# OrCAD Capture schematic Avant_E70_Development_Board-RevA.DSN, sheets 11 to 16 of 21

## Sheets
11 Bank-9,10,11 LPDDR4: size D; title: Bank-9,10,11 LPDDR4
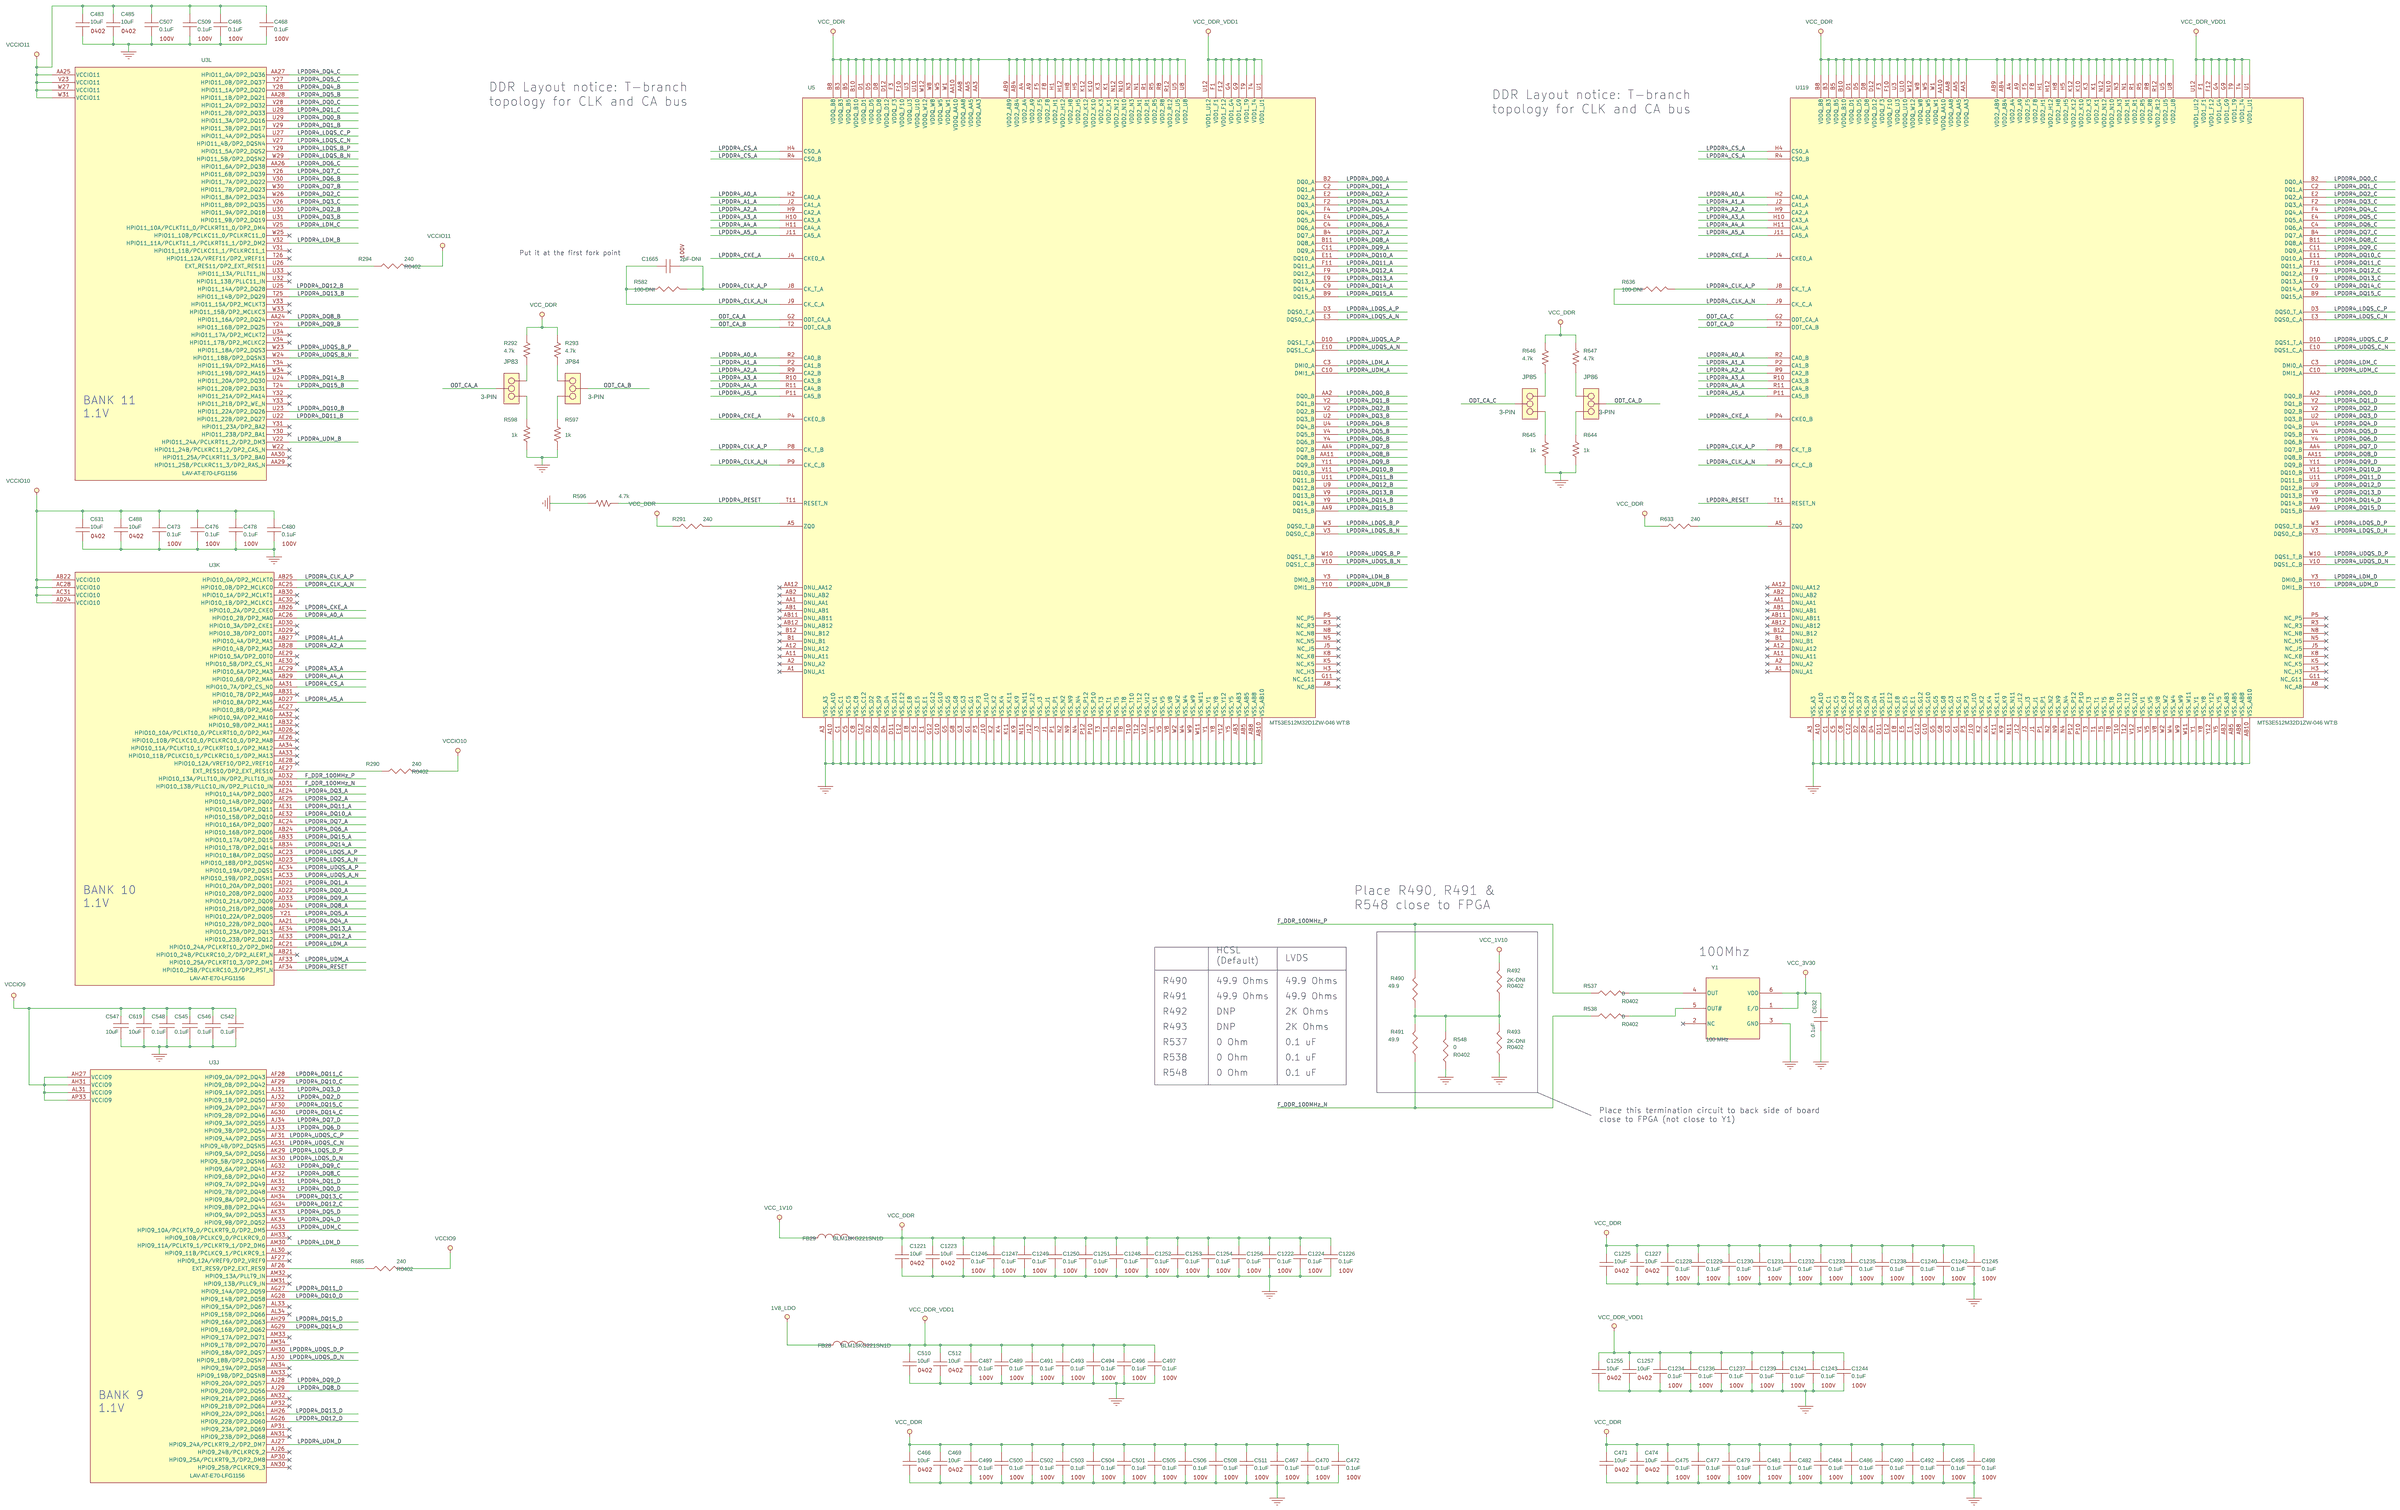
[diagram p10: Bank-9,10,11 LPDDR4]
12 Bank-12,13 PMODs: size B; title: Bank-12,13 PMODs
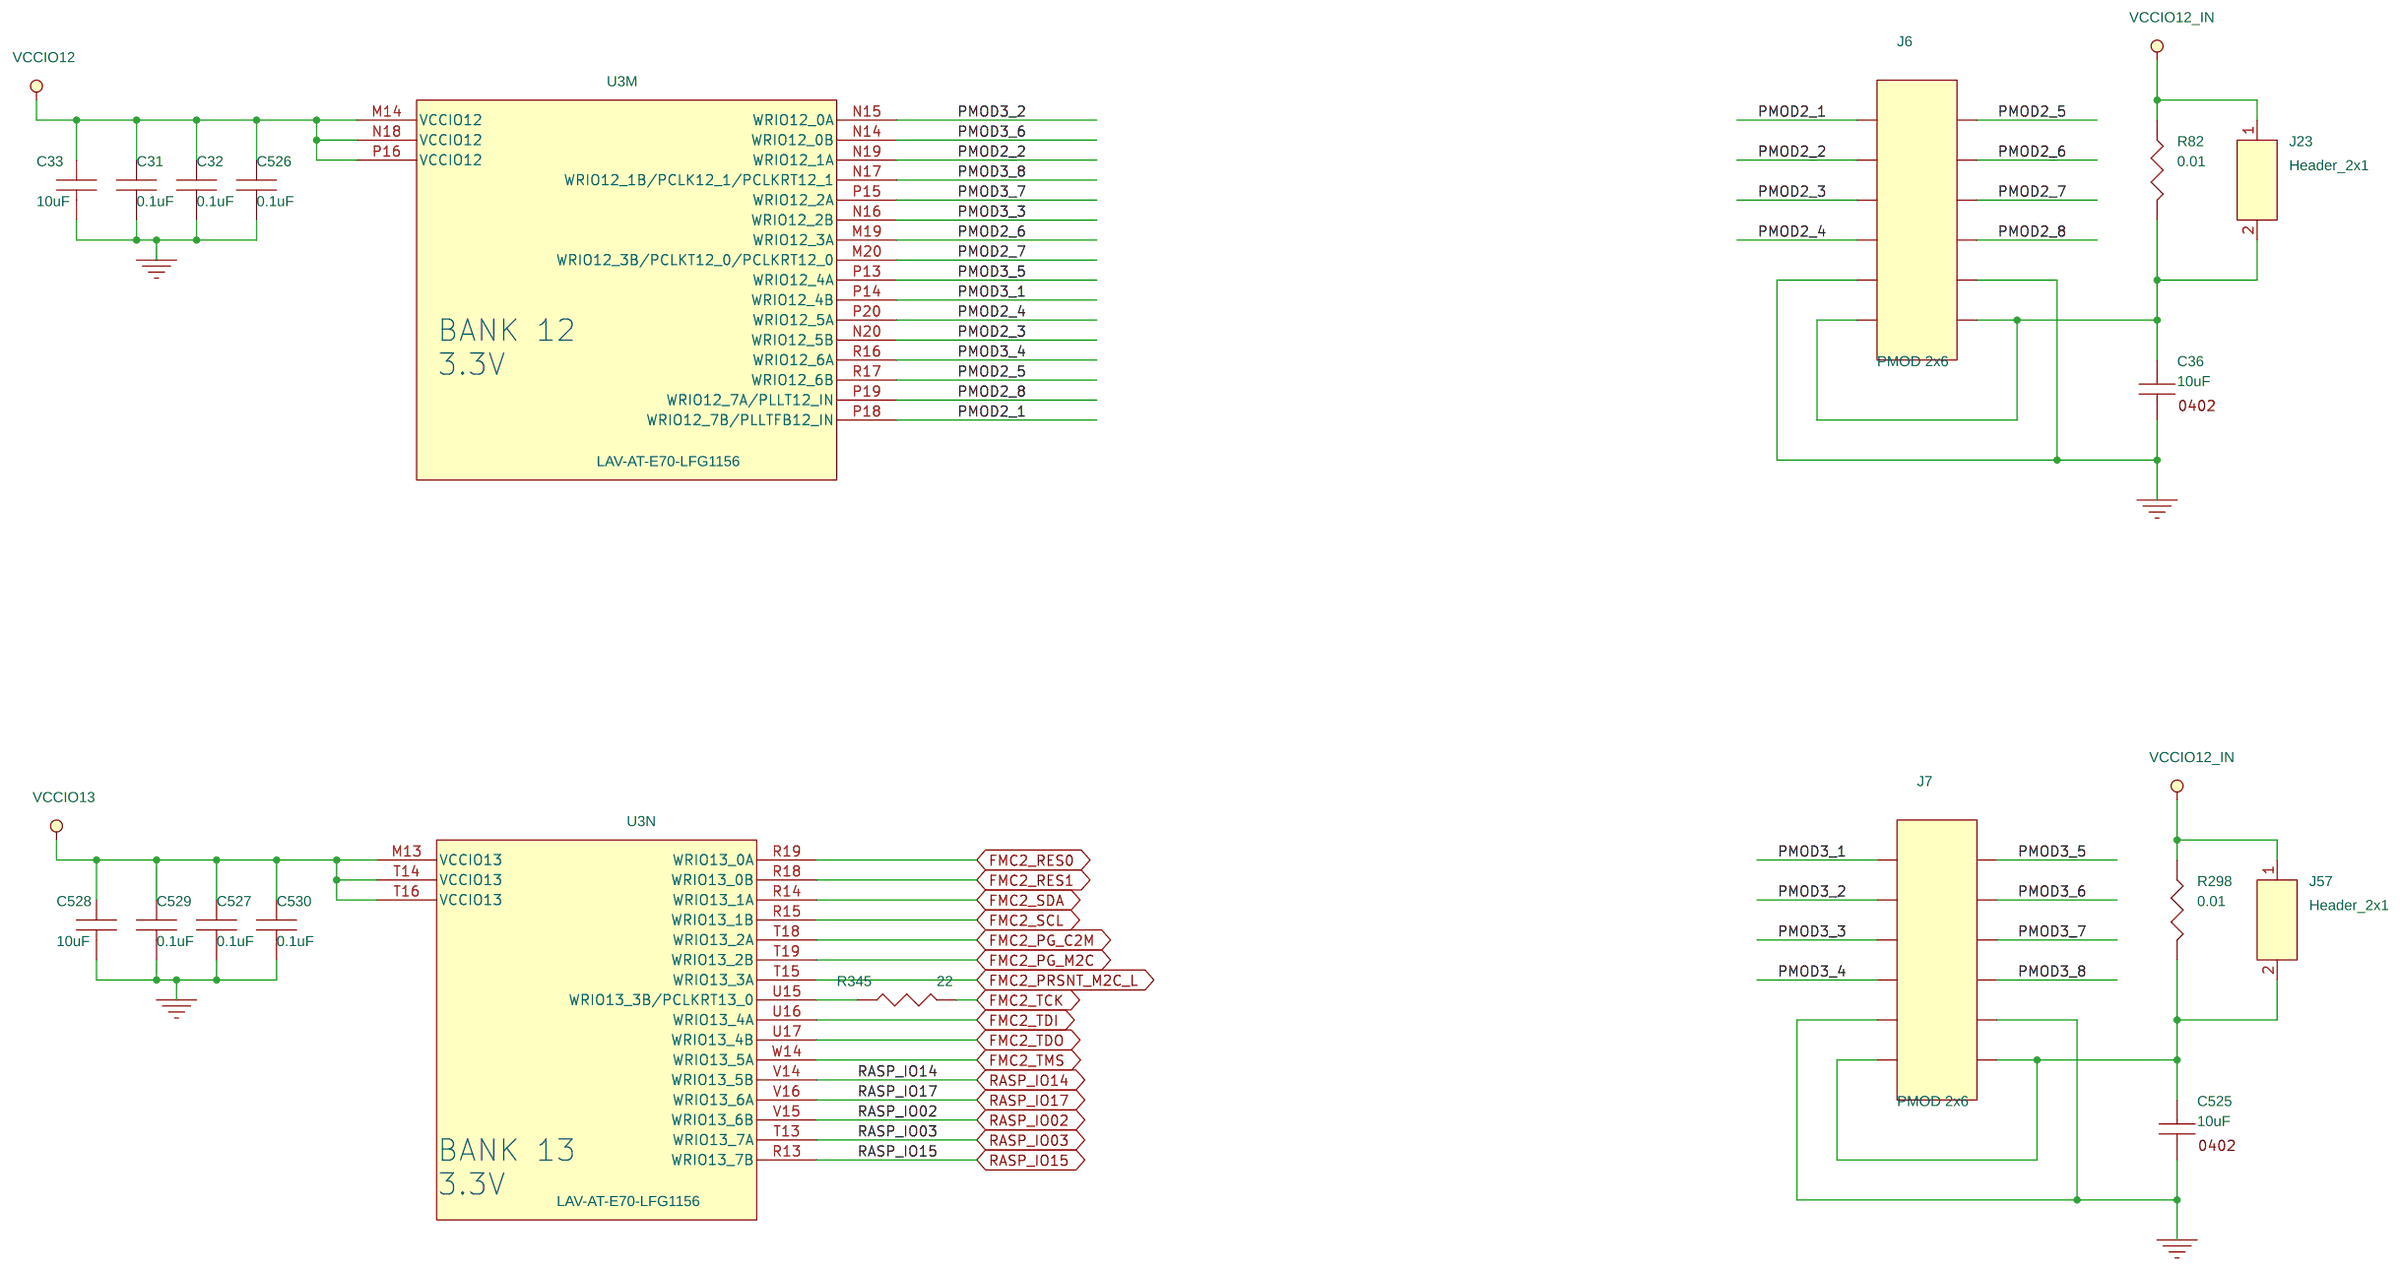
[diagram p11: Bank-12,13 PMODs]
13 Bank-14 Segment & RPi: size B; title: Bank-14 Segment & RPi
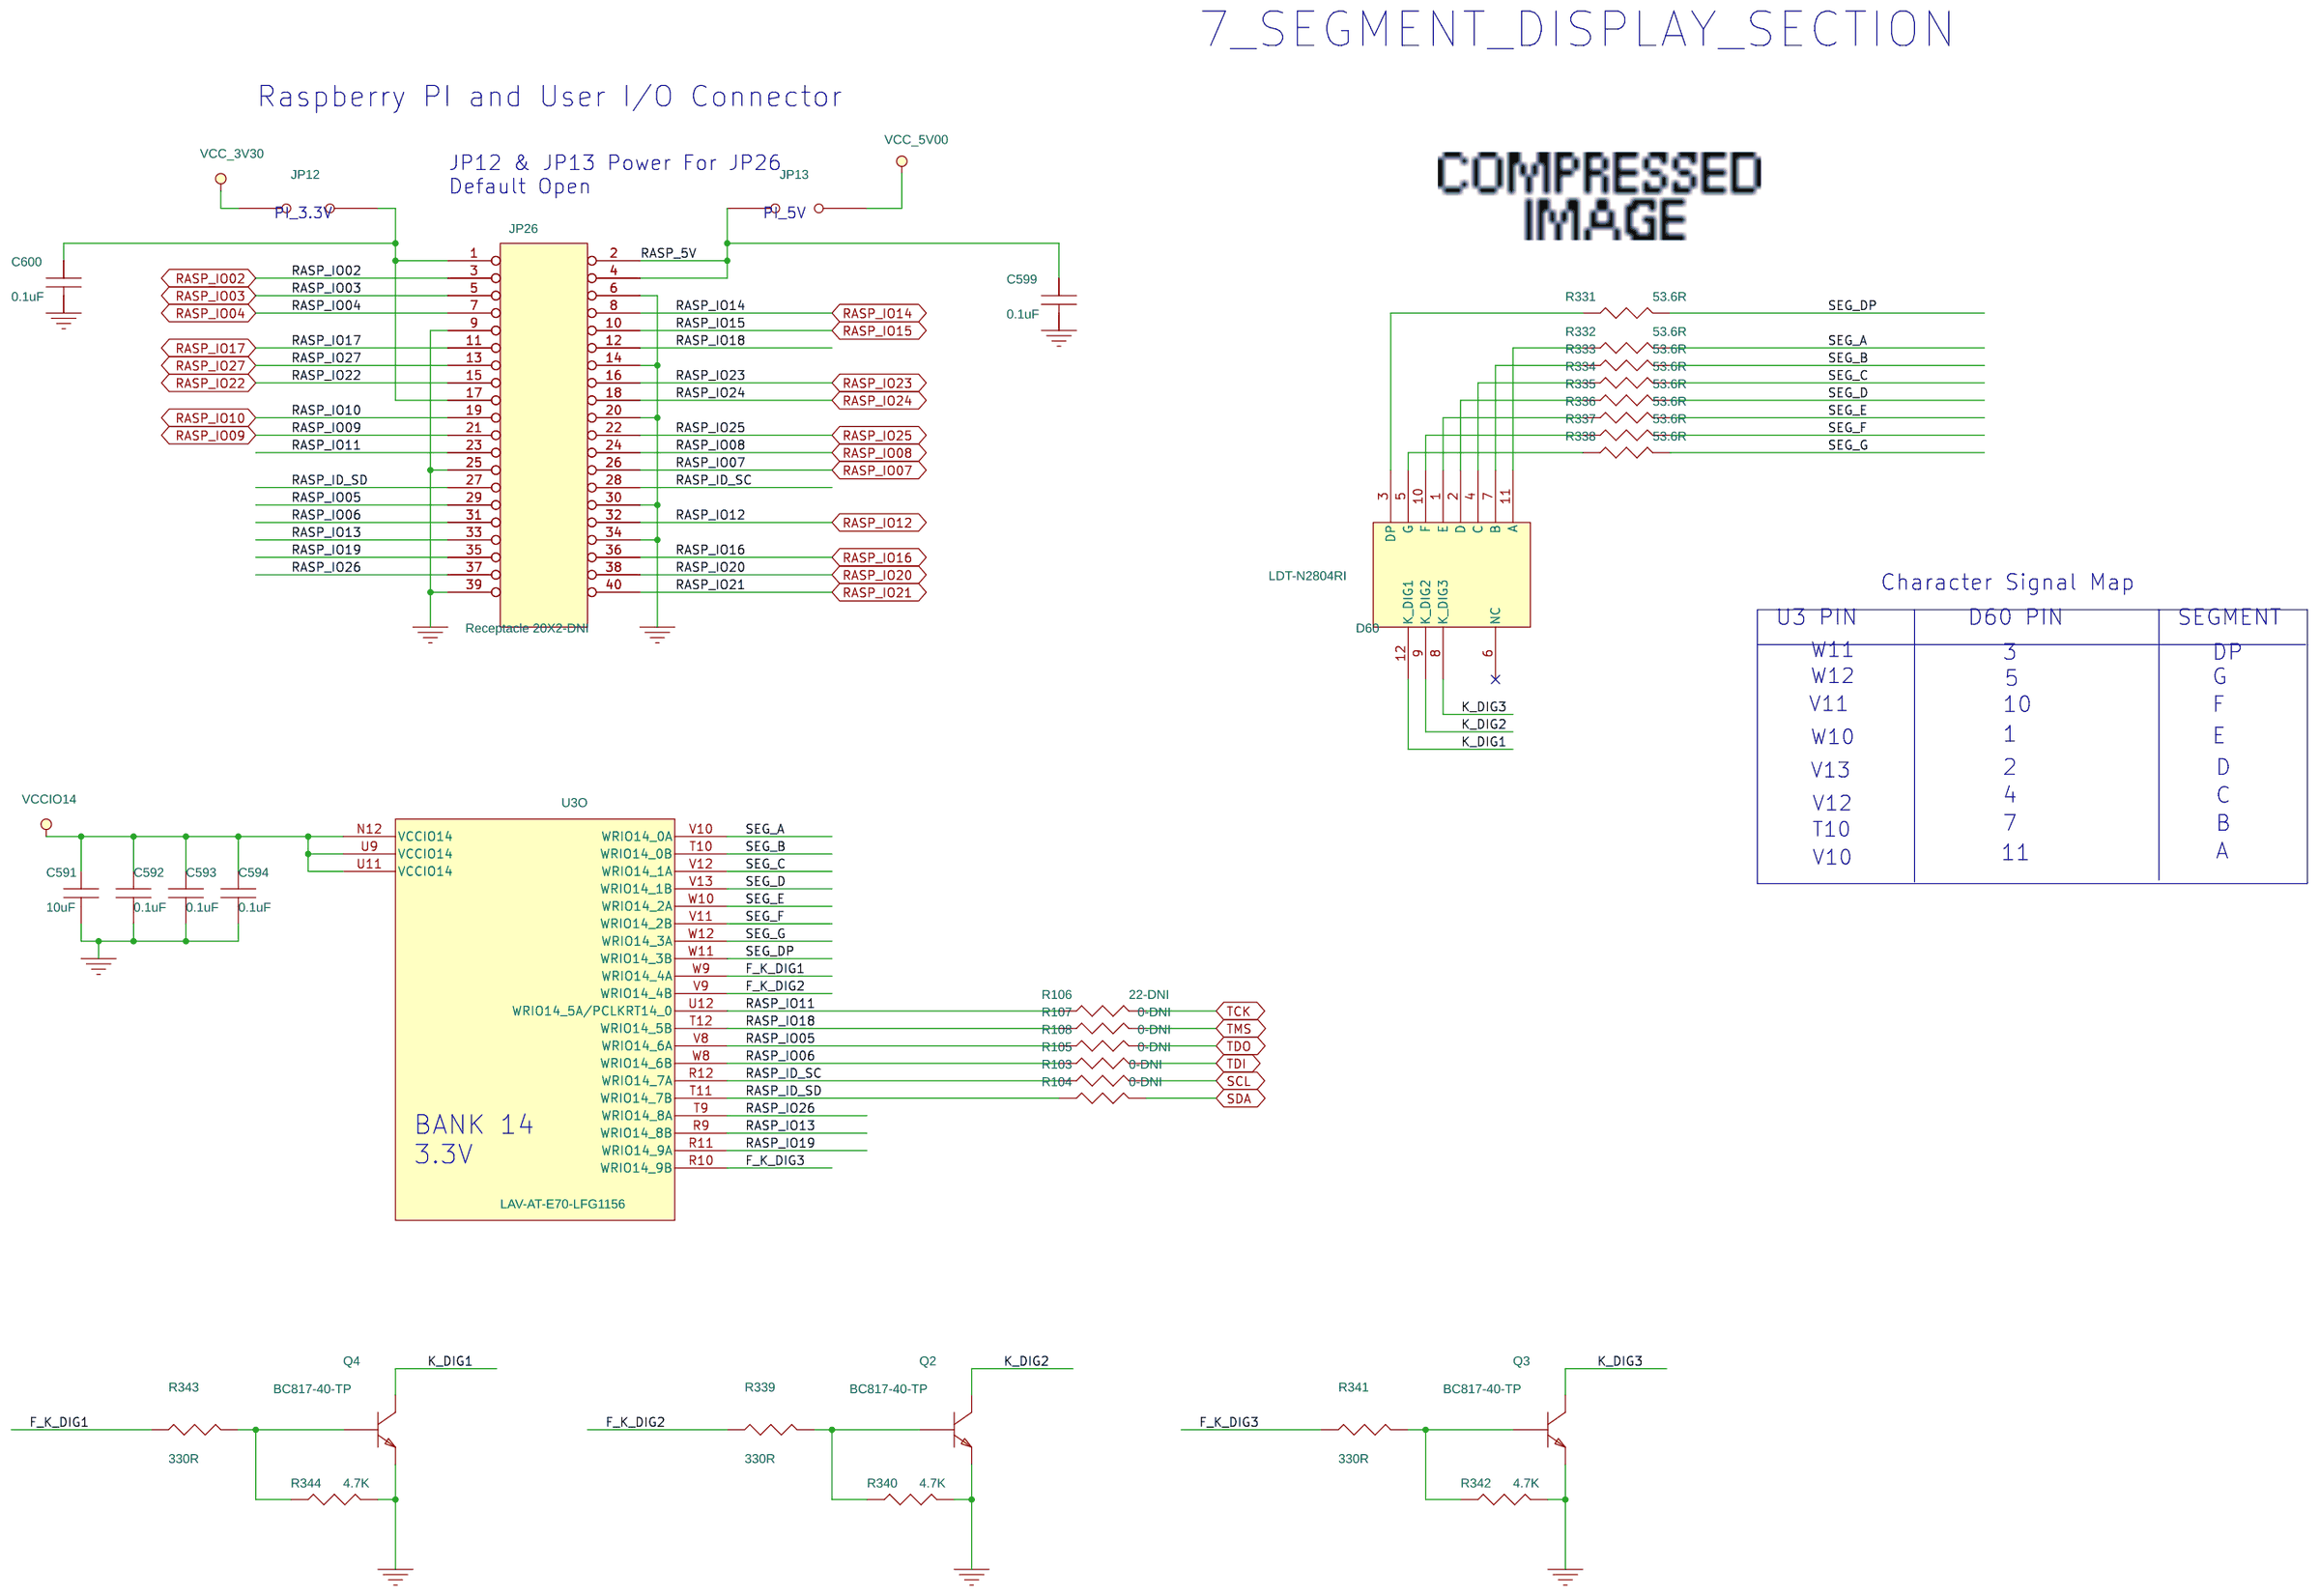
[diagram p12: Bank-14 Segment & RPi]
14 Bank Power: size B; title: Bank Power
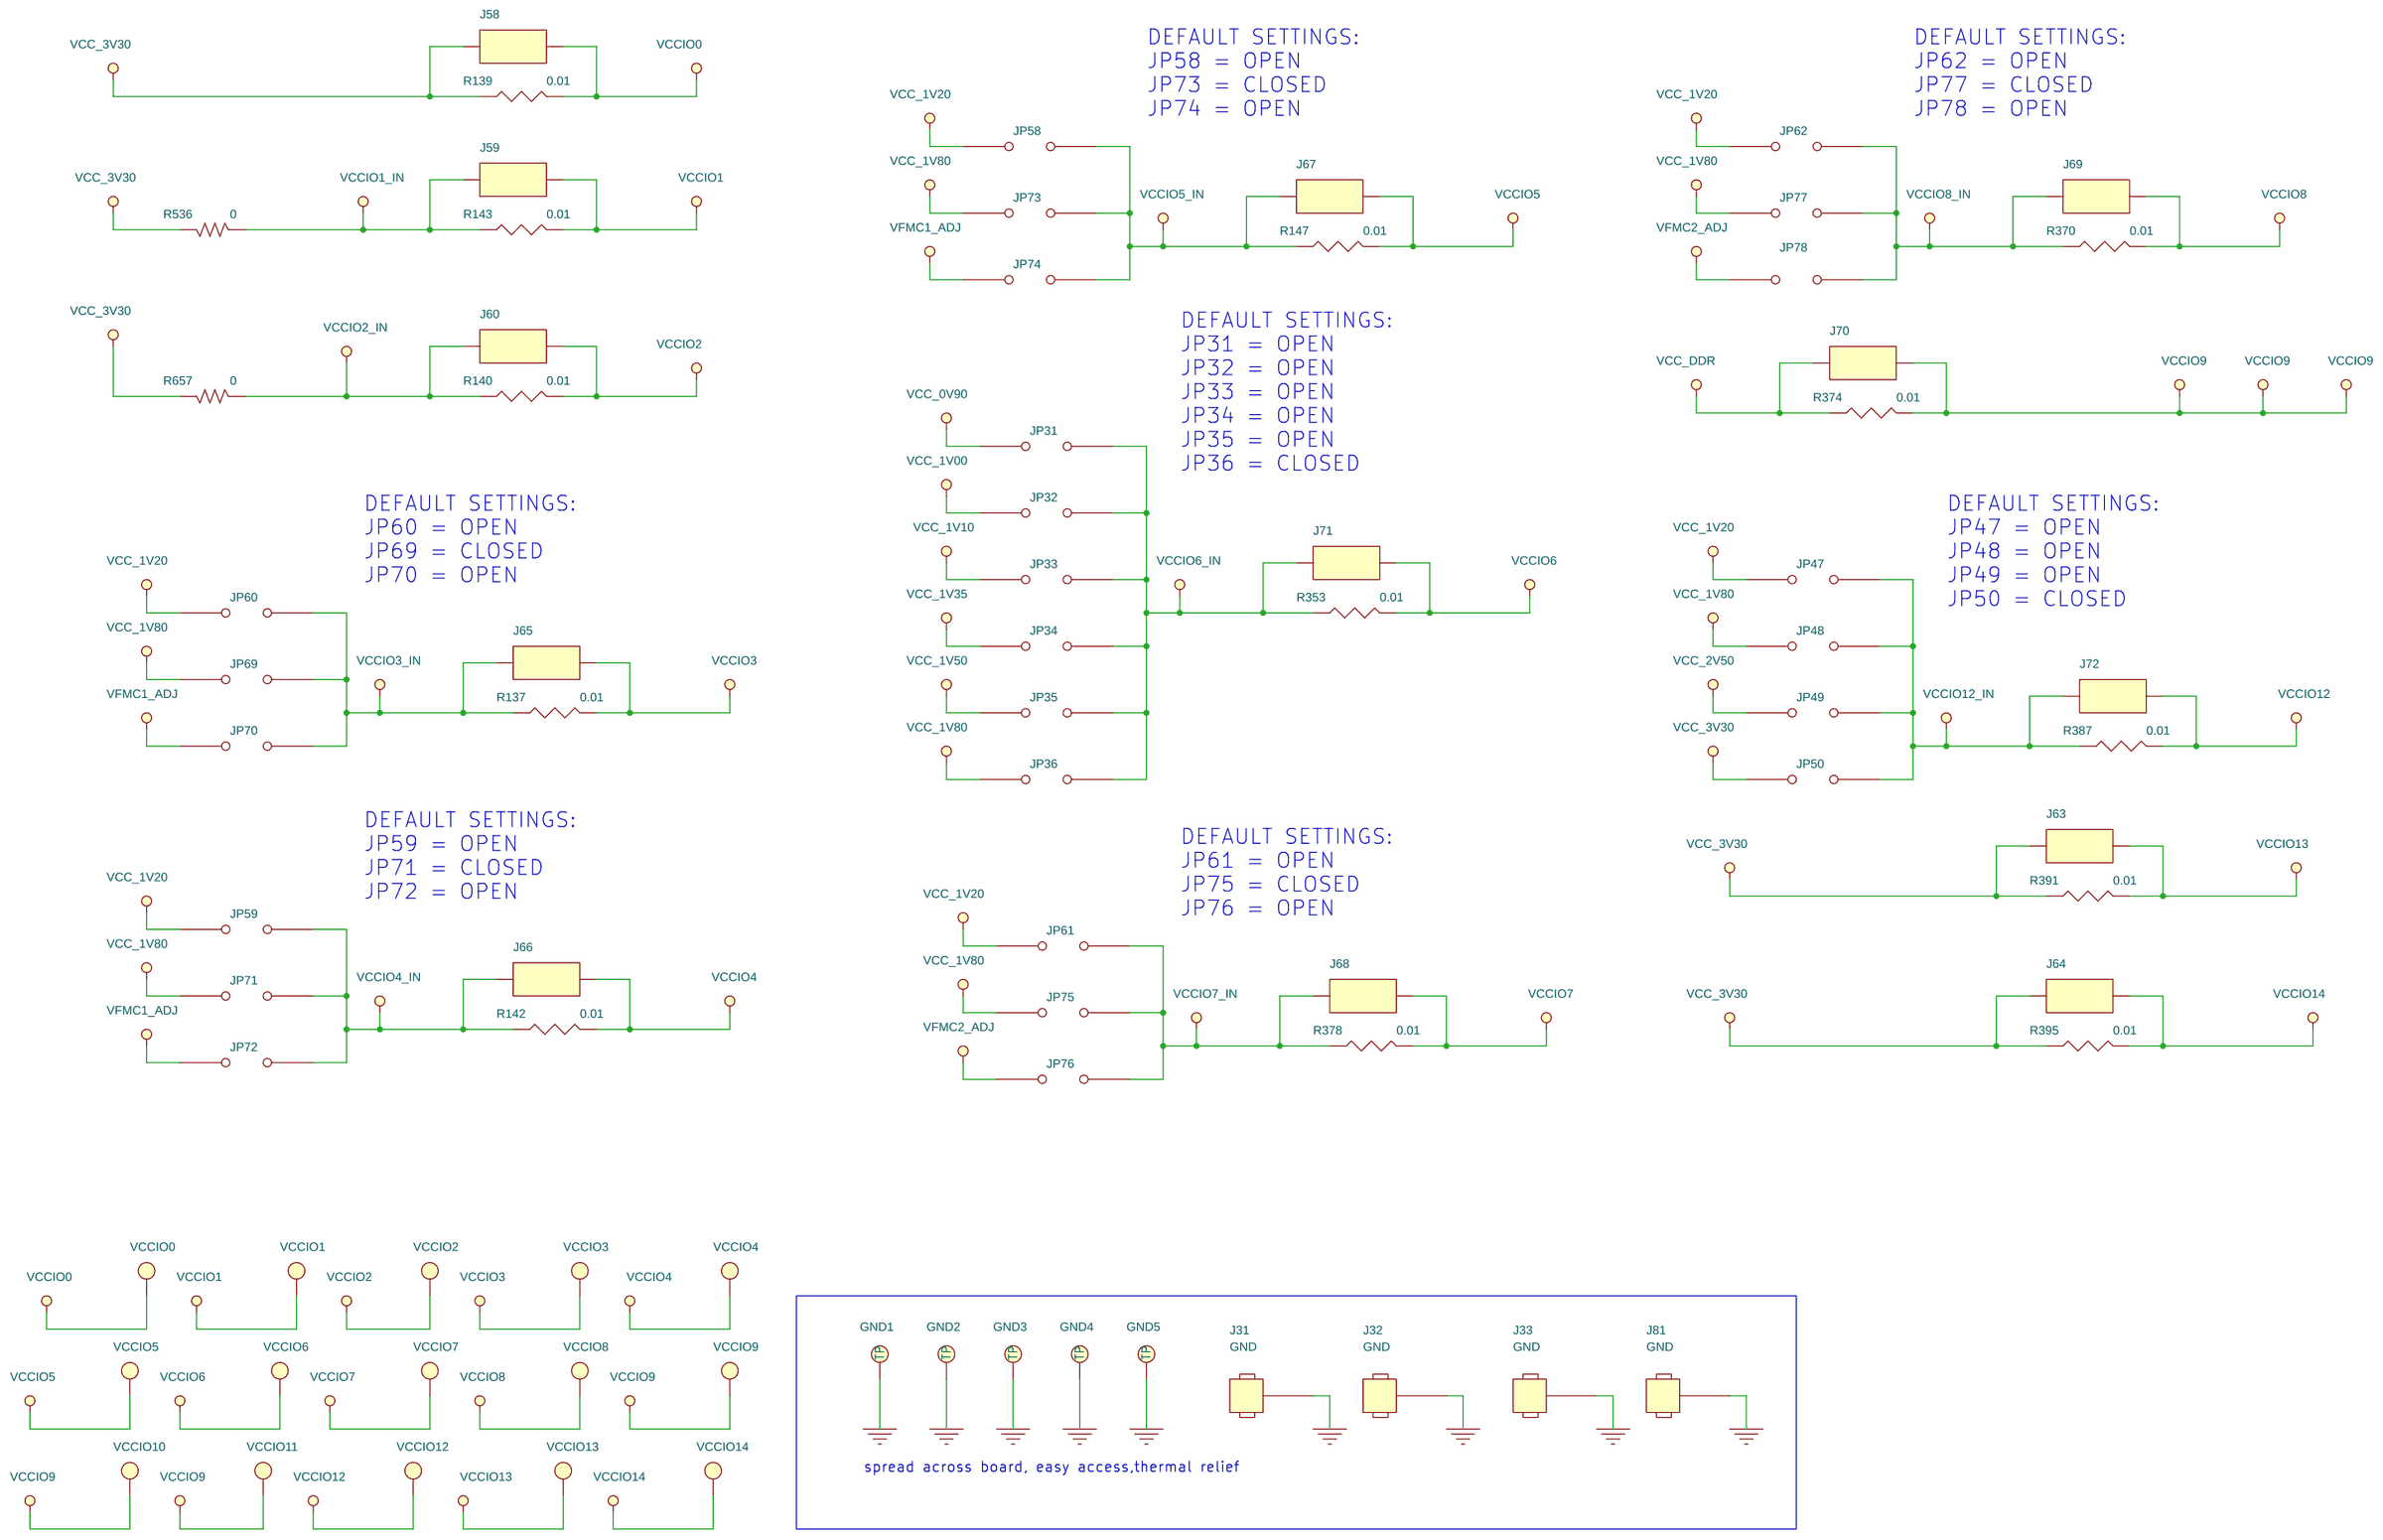
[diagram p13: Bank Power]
15 Power Decoupling: size B; title: Power Decoupling
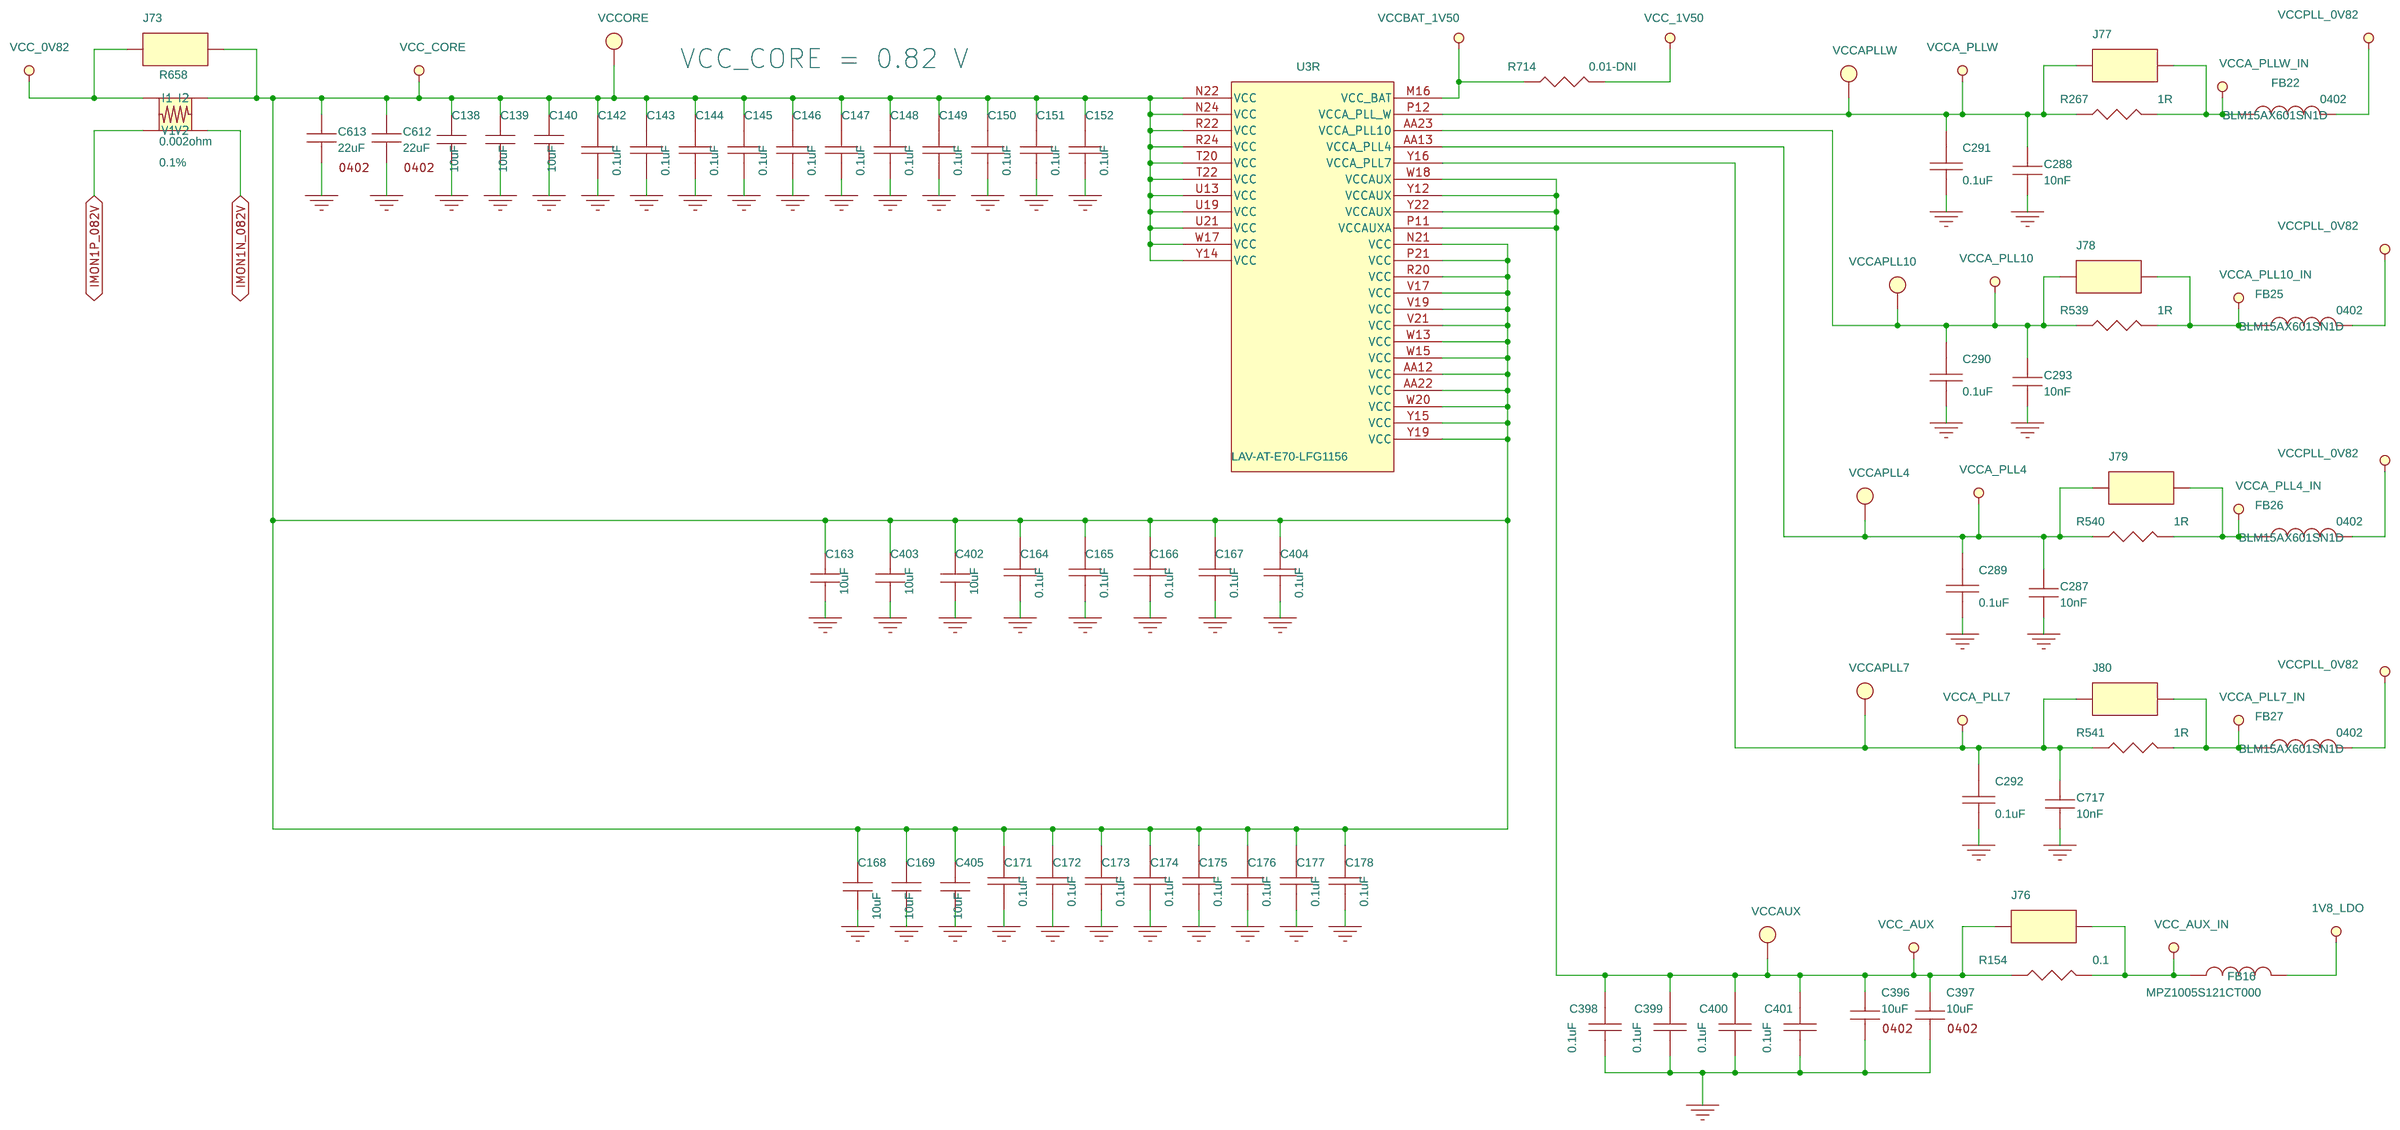
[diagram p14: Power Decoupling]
16 Power Supplies 1: size C; title: Power Supplies 1
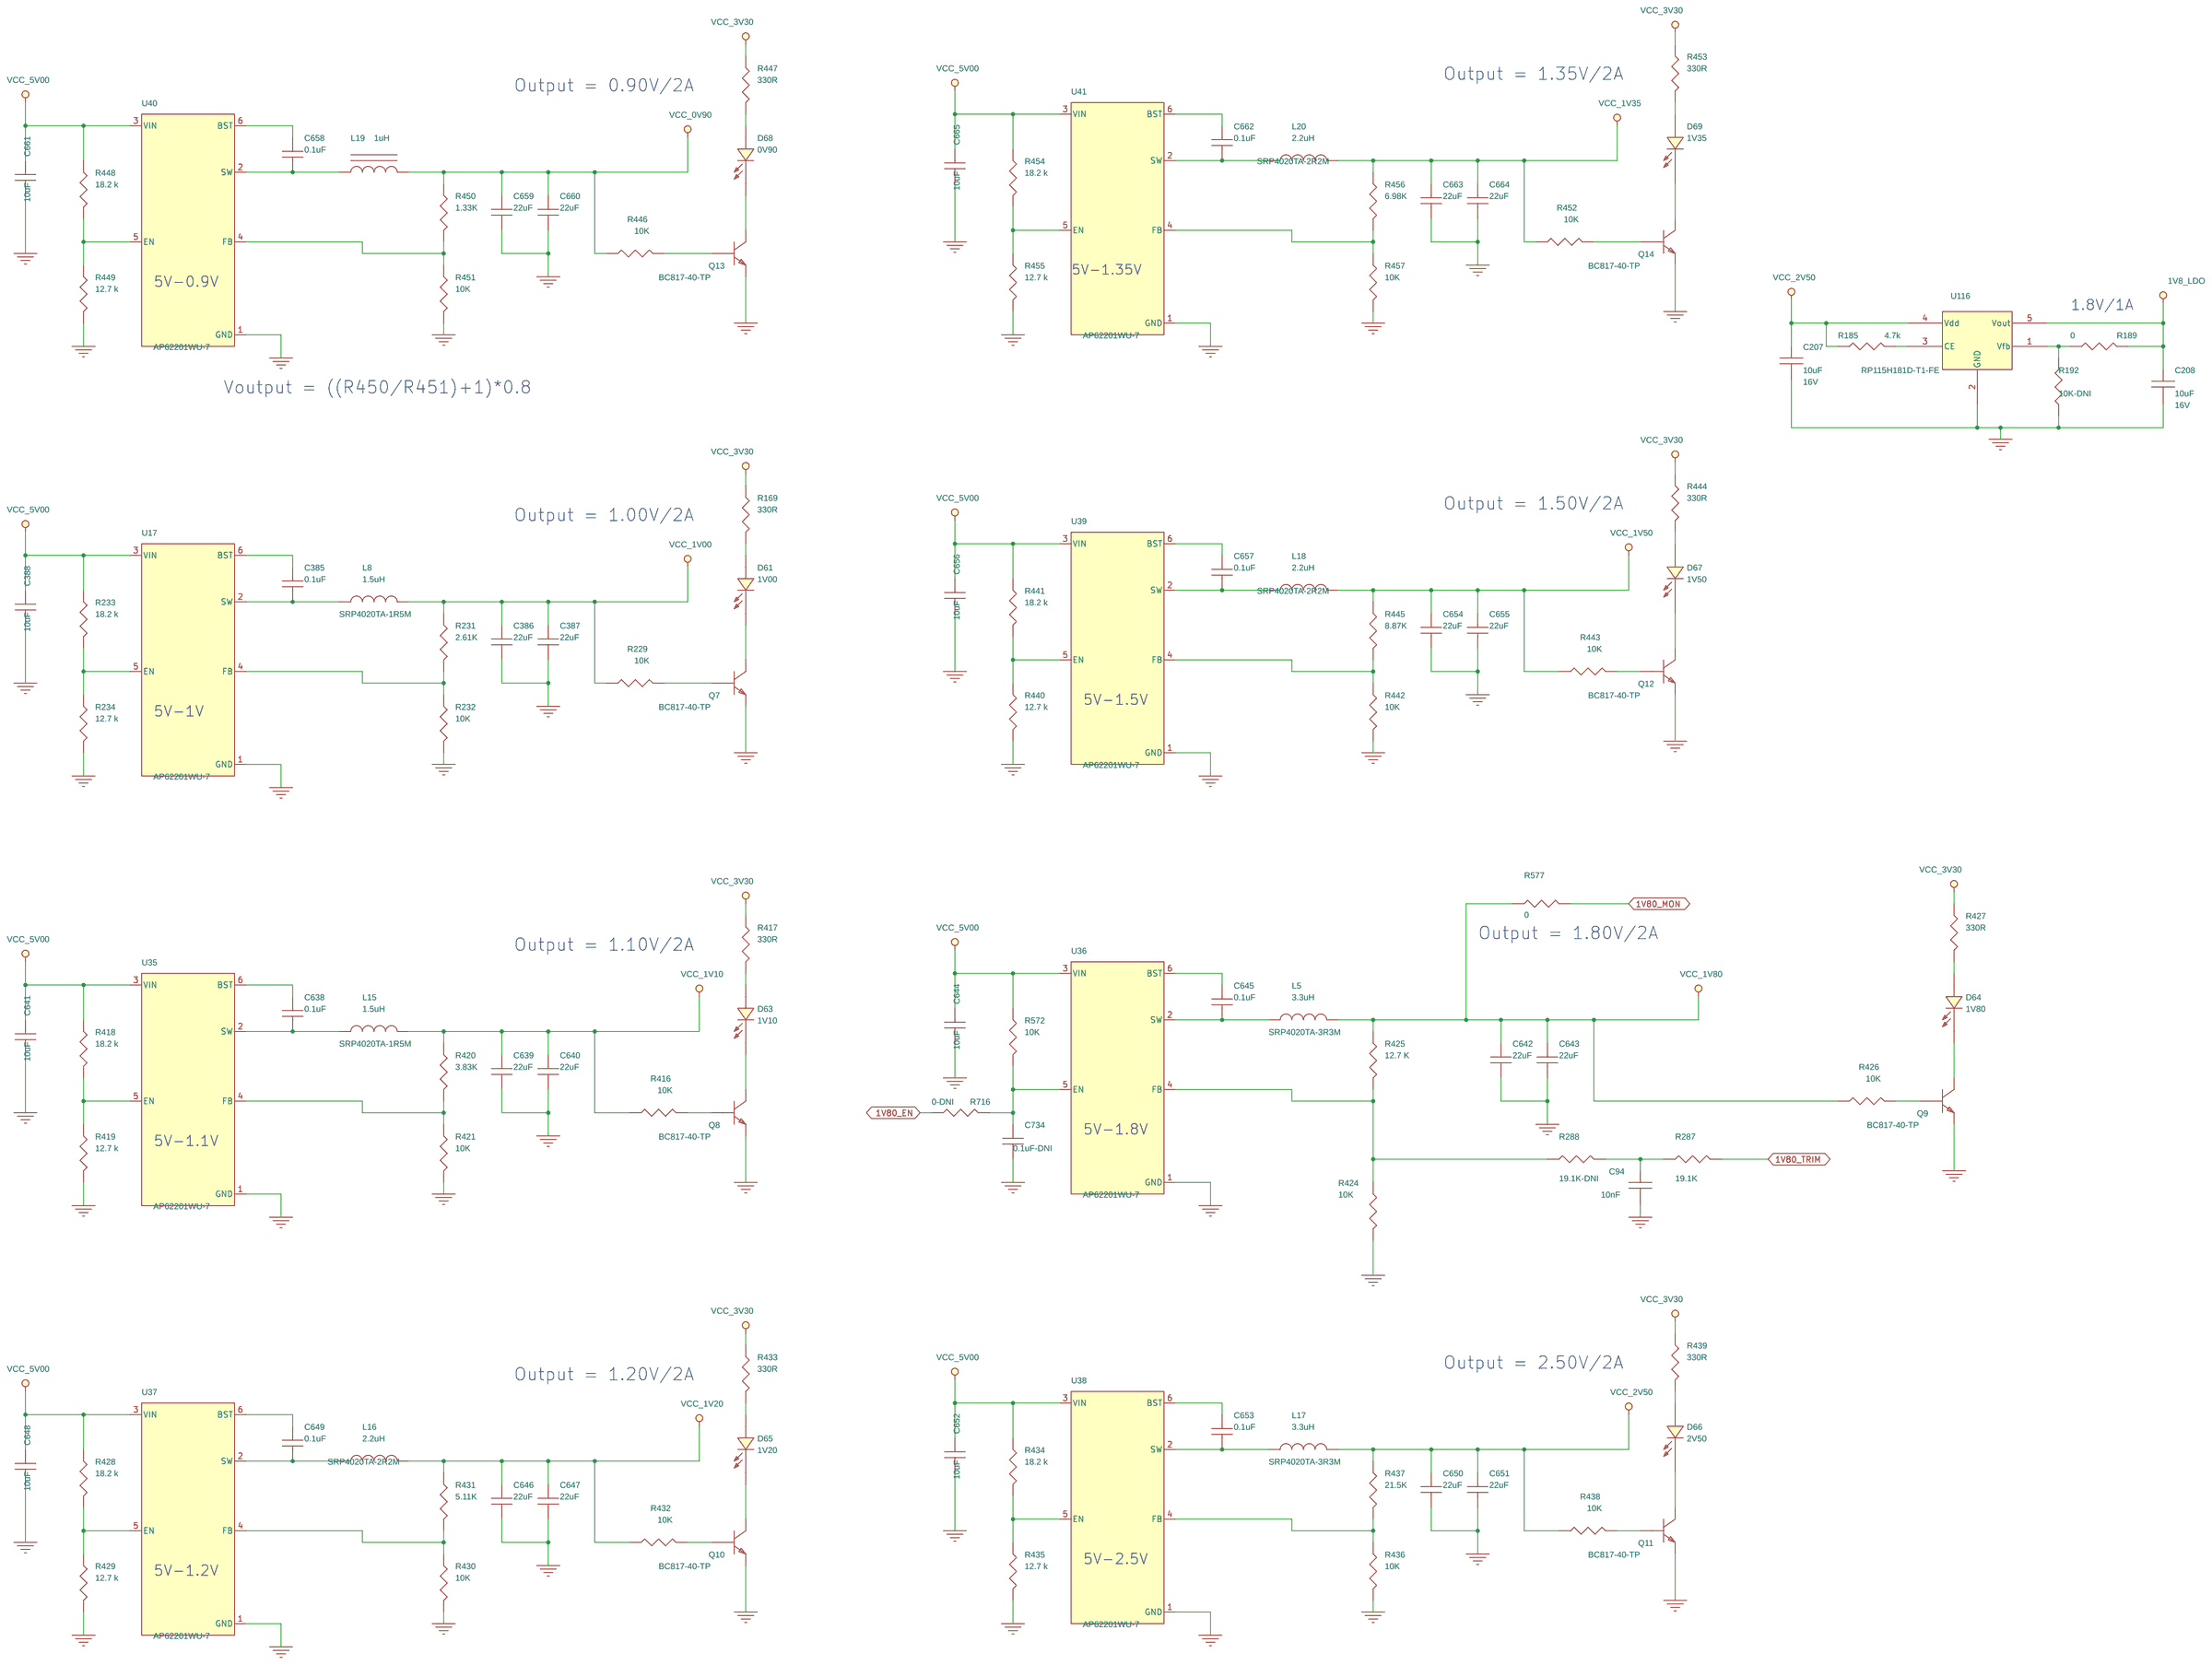
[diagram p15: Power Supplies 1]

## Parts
sheet Bank Power
GND1  TestPoint_Hole  [TP]
GND2  TestPoint_Hole  [TP]
GND3  TestPoint_Hole  [TP]
GND4  TestPoint_Hole  [TP]
GND5  TestPoint_Hole  [TP]
J31  GND  [TUR_TH]
J32  GND  [TUR_TH]
J33  GND  [TUR_TH]
J58  J-Header_2x1  [Header_2X1_100MIL]
J59  J-Header_2x1  [Header_2X1_100MIL]
J60  J-Header_2x1  [Header_2X1_100MIL]
J63  J-Header_2x1  [Header_2X1_100MIL]
J64  J-Header_2x1  [Header_2X1_100MIL]
J65  J-Header_2x1  [Header_2X1_100MIL]
J66  J-Header_2x1  [Header_2X1_100MIL]
J67  J-Header_2x1  [Header_2X1_100MIL]
J68  J-Header_2x1  [Header_2X1_100MIL]
J69  J-Header_2x1  [Header_2X1_100MIL]
J70  J-Header_2x1  [Header_2X1_100MIL]
J71  J-Header_2x1  [Header_2X1_100MIL]
J72  J-Header_2x1  [Header_2X1_100MIL]
J81  GND  [TUR_TH]
JP31  J-2 Pin Jumper  [0p1_2-Pin_TH]
JP32  J-2 Pin Jumper  [0p1_2-Pin_TH]
JP33  J-2 Pin Jumper  [0p1_2-Pin_TH]
JP34  J-2 Pin Jumper  [0p1_2-Pin_TH]
JP35  J-2 Pin Jumper  [0p1_2-Pin_TH]
JP36  J-2 Pin Jumper  [0p1_2-Pin_TH]
JP47  J-2 Pin Jumper  [0p1_2-Pin_TH]
JP48  J-2 Pin Jumper  [0p1_2-Pin_TH]
JP49  J-2 Pin Jumper  [0p1_2-Pin_TH]
JP50  J-2 Pin Jumper  [0p1_2-Pin_TH]
JP58  J-2 Pin Jumper  [0p1_2-Pin_TH]
JP59  J-2 Pin Jumper  [0p1_2-Pin_TH]
JP60  J-2 Pin Jumper  [0p1_2-Pin_TH]
JP61  J-2 Pin Jumper  [0p1_2-Pin_TH]
JP62  J-2 Pin Jumper  [0p1_2-Pin_TH]
JP69  J-2 Pin Jumper  [0p1_2-Pin_TH]
JP70  J-2 Pin Jumper  [0p1_2-Pin_TH]
JP71  J-2 Pin Jumper  [0p1_2-Pin_TH]
JP72  J-2 Pin Jumper  [0p1_2-Pin_TH]
JP73  J-2 Pin Jumper  [0p1_2-Pin_TH]
JP74  J-2 Pin Jumper  [0p1_2-Pin_TH]
JP75  J-2 Pin Jumper  [0p1_2-Pin_TH]
JP76  J-2 Pin Jumper  [0p1_2-Pin_TH]
JP77  J-2 Pin Jumper  [0p1_2-Pin_TH]
JP78  J-2 Pin Jumper  [0p1_2-Pin_TH]
R137  0.01  [R0603]
R139  0.01  [R0603]
R140  0.01  [R0603]
R142  0.01  [R0603]
R143  0.01  [R0603]
R147  0.01  [R0603]
R353  0.01  [R0603]
R370  0.01  [R0603]
R374  0.01  [R0603]
R378  0.01  [R0603]
R387  0.01  [R0603]
R391  0.01  [R0603]
R395  0.01  [R0603]
R536  0  [R0402]
R657  0  [R0402]
VCCIO0  TestPoint_SMT  [TPC32]
VCCIO1  TestPoint_SMT  [TPC32]
VCCIO2  TestPoint_SMT  [TPC32]
VCCIO3  TestPoint_SMT  [TPC32]
VCCIO4  TestPoint_SMT  [TPC32]
VCCIO5  TestPoint_SMT  [TPC32]
VCCIO6  TestPoint_SMT  [TPC32]
VCCIO7  TestPoint_SMT  [TPC32]
VCCIO8  TestPoint_SMT  [TPC32]
VCCIO9  TestPoint_SMT  [TPC32]
VCCIO10  TestPoint_SMT  [TPC32]
VCCIO11  TestPoint_SMT  [TPC32]
VCCIO12  TestPoint_SMT  [TPC32]
VCCIO13  TestPoint_SMT  [TPC32]
VCCIO14  TestPoint_SMT  [TPC32]
sheet Bank-9,10,11 LPDDR4
C465  0.1uF  [C0201]
C466  10uF  [C0402]
C467  0.1uF  [C0201]
C468  0.1uF  [C0201]
C469  10uF  [C0402]
C470  0.1uF  [C0201]
C471  10uF  [C0402]
C472  0.1uF  [C0201]
C473  0.1uF  [C0201]
C474  10uF  [C0402]
C475  0.1uF  [C0201]
C476  0.1uF  [C0201]
C477  0.1uF  [C0201]
C478  0.1uF  [C0201]
C479  0.1uF  [C0201]
C480  0.1uF  [C0201]
C481  0.1uF  [C0201]
C482  0.1uF  [C0201]
C483  10uF  [C0402]
C484  0.1uF  [C0201]
C485  10uF  [C0402]
C486  0.1uF  [C0201]
C487  0.1uF  [C0201]
C488  10uF  [C0402]
C489  0.1uF  [C0201]
C490  0.1uF  [C0201]
C491  0.1uF  [C0201]
C492  0.1uF  [C0201]
C493  0.1uF  [C0201]
C494  0.1uF  [C0201]
C495  0.1uF  [C0201]
C496  0.1uF  [C0201]
C497  0.1uF  [C0201]
C498  0.1uF  [C0201]
C499  0.1uF  [C0201]
C500  0.1uF  [C0201]
C501  0.1uF  [C0201]
C502  0.1uF  [C0201]
C503  0.1uF  [C0201]
C504  0.1uF  [C0201]
C505  0.1uF  [C0201]
C506  0.1uF  [C0201]
C507  0.1uF  [C0201]
C508  0.1uF  [C0201]
C509  0.1uF  [C0201]
C510  10uF  [C0402]
C511  0.1uF  [C0201]
C512  10uF  [C0402]
C542  0.1uF  [C0201]
C545  0.1uF  [C0201]
C546  0.1uF  [C0201]
C547  10uF  [C0402]
C548  0.1uF  [C0201]
C619  10uF  [C0402]
C631  10uF  [C0402]
C632  0.1uF  [C0402]
C1221  10uF  [C0402]
C1222  0.1uF  [C0201]
C1223  10uF  [C0402]
C1224  0.1uF  [C0201]
C1225  10uF  [C0402]
C1226  0.1uF  [C0201]
C1227  10uF  [C0402]
C1228  0.1uF  [C0201]
C1229  0.1uF  [C0201]
C1230  0.1uF  [C0201]
C1231  0.1uF  [C0201]
C1232  0.1uF  [C0201]
C1233  0.1uF  [C0201]
C1234  0.1uF  [C0201]
C1235  0.1uF  [C0201]
C1236  0.1uF  [C0201]
C1237  0.1uF  [C0201]
C1238  0.1uF  [C0201]
C1239  0.1uF  [C0201]
C1240  0.1uF  [C0201]
C1241  0.1uF  [C0201]
C1242  0.1uF  [C0201]
C1243  0.1uF  [C0201]
C1244  0.1uF  [C0201]
C1245  0.1uF  [C0201]
C1246  0.1uF  [C0201]
C1247  0.1uF  [C0201]
C1248  0.1uF  [C0201]
C1249  0.1uF  [C0201]
C1250  0.1uF  [C0201]
C1251  0.1uF  [C0201]
C1252  0.1uF  [C0201]
C1253  0.1uF  [C0201]
C1254  0.1uF  [C0201]
C1255  10uF  [C0402]
C1256  0.1uF  [C0201]
C1257  10uF  [C0402]
C1665  2pF-DNI  [C0201]
FB28  BLM18KG221SN1D  [FB0603]
FB29  BLM18KG221SN1D  [FB0603]
JP83  3-PIN  [HDR254M-1X3]
JP84  3-PIN  [HDR254M-1X3]
JP85  3-PIN  [HDR254M-1X3]
JP86  3-PIN  [HDR254M-1X3]
R290  240  [R0402]
R291  240  [R0402]
R292  4.7k  [R0603]
R293  4.7k  [R0603]
R294  240  [R0402]
R490  49.9  [R0402]
R491  49.9  [R0402]
R492  2K-DNI  [R0402]
R493  2K-DNI  [R0402]
R537  0  [R0402]
R538  0  [R0402]
R548  0  [R0402]
R582  100-DNI  [R0201]
R596  4.7k  [R0603]
R597  1k  [R0402]
R598  1k  [R0402]
R633  240  [R0402]
R636  100-DNI  [R0201]
R644  1k  [R0402]
R645  1k  [R0402]
R646  4.7k  [R0603]
R647  4.7k  [R0603]
R685  240  [R0402]
U5  MT53E512M32D1ZW-046 WT:B  [BGA_SDRAM_200]
U119  MT53E512M32D1ZW-046 WT:B  [BGA_SDRAM_200]
Y1  100 MHz  [SMD6_AX3HAF1]
sheet Bank-12,13 PMODs
C31  0.1uF  [C0201]
C32  0.1uF  [C0201]
C33  10uF  [C0402]
C36  10uF  [C0402]
C525  10uF  [C0402]
C526  0.1uF  [C0201]
C527  0.1uF  [C0201]
C528  10uF  [C0402]
C529  0.1uF  [C0201]
C530  0.1uF  [C0201]
J6  PMOD 2x6  [PPPC062LJBN-RC]
J7  PMOD 2x6  [PPPC062LJBN-RC]
J23  Header_2x1  [Header_2x1]
J57  Header_2x1  [Header_2x1]
R82  0.01  [R0603]
R298  0.01  [R0603]
R345  22  [R0402]
U3  LAV-AT-E70-LFG1156  [LAV-AT-500-L_1156]  (sections A,B,C,D,E,F,G,H,I,J,K,L,M,N,O,P,Q,R,S,T,U)
sheet Bank-14 Segment & RPi
C591  10uF  [C0402]
C592  0.1uF  [C0201]
C593  0.1uF  [C0201]
C594  0.1uF  [C0201]
C599  0.1uF  [C0201]
C600  0.1uF  [C0201]
D60  LDT-N2804RI  [display_12P-PTH]
JP12  JUMPER-DNI  [Header_1x2]
JP13  JUMPER-DNI  [Header_1x2]
JP26  Receptacle 20X2-DNI  [HDR254-2X20_socket]
Q2  BC817-40-TP  [SOT23-3]
Q3  BC817-40-TP  [SOT23-3]
Q4  BC817-40-TP  [SOT23-3]
R103  0-DNI  [R0603]
R104  0-DNI  [R0603]
R105  0-DNI  [R0402]
R106  22-DNI  [R0402]
R107  0-DNI  [R0402]
R108  0-DNI  [R0402]
R331  53.6R  [res0402]
R332  53.6R  [res0402]
R333  53.6R  [res0402]
R334  53.6R  [res0402]
R335  53.6R  [res0402]
R336  53.6R  [res0402]
R337  53.6R  [res0402]
R338  53.6R  [res0402]
R339  330R  [R0603]
R340  4.7K  [R0603]
R341  330R  [R0603]
R342  4.7K  [R0603]
R343  330R  [R0603]
R344  4.7K  [R0603]
sheet Power Decoupling
C138  10uF  [C0402]
C139  10uF  [C0402]
C140  10uF  [C0402]
C142  0.1uF  [C0201]
C143  0.1uF  [C0201]
C144  0.1uF  [C0201]
C145  0.1uF  [C0201]
C146  0.1uF  [C0201]
C147  0.1uF  [C0201]
C148  0.1uF  [C0201]
C149  0.1uF  [C0201]
C150  0.1uF  [C0201]
C151  0.1uF  [C0201]
C152  0.1uF  [C0201]
C163  10uF  [C0402]
C164  0.1uF  [C0201]
C165  0.1uF  [C0201]
C166  0.1uF  [C0201]
C167  0.1uF  [C0201]
C168  10uF  [C0402]
C169  10uF  [C0402]
C171  0.1uF  [C0201]
C172  0.1uF  [C0201]
C173  0.1uF  [C0201]
C174  0.1uF  [C0201]
C175  0.1uF  [C0201]
C176  0.1uF  [C0201]
C177  0.1uF  [C0201]
C178  0.1uF  [C0201]
C287  10nF  [C0402]
C288  10nF  [C0402]
C289  0.1uF  [C0201]
C290  0.1uF  [C0201]
C291  0.1uF  [C0201]
C292  0.1uF  [C0201]
C293  10nF  [C0402]
C396  10uF  [C0402]
C397  10uF  [C0402]
C398  0.1uF  [C0201]
C399  0.1uF  [C0201]
C400  0.1uF  [C0201]
C401  0.1uF  [C0201]
C402  10uF  [C0402]
C403  10uF  [C0402]
C404  0.1uF  [C0201]
C405  10uF  [C0402]
C612  22uF  [C0603]
C613  22uF  [C0603]
C717  10nF  [C0402]
FB16  MPZ1005S121CT000  [FB0402]
FB22  BLM15AX601SN1D  [0402]
FB25  BLM15AX601SN1D  [0402]
FB26  BLM15AX601SN1D  [0402]
FB27  BLM15AX601SN1D  [0402]
J73  J-Header_2x1  [Header_2X1_100MIL]
J76  J-Header_2x1  [Header_2X1_100MIL]
J77  J-Header_2x1  [Header_2X1_100MIL]
J78  J-Header_2x1  [Header_2X1_100MIL]
J79  J-Header_2x1  [Header_2X1_100MIL]
J80  J-Header_2x1  [Header_2X1_100MIL]
R154  0.1  [0603]
R267  1R  [0603]
R539  1R  [0603]
R540  1R  [0603]
R541  1R  [0603]
R658  0.002ohm  [R3637]
R714  0.01-DNI  [R0603]
VCCAPLL4  TestPoint_SMT  [TPC32]
VCCAPLL7  TestPoint_SMT  [TPC32]
VCCAPLL10  TestPoint_SMT  [TPC32]
VCCAPLLW  TestPoint_SMT  [TPC32]
VCCAUX  TestPoint_SMT  [TPC32]
VCCORE  TestPoint_SMT  [TPC32]
sheet Power Supplies 1
C94  10nF  [C0402]
C207  10uF  [C0603]
C208  10uF  [C0603]
C385  0.1uF  [C0402]
C386  22uF  [C0603]
C387  22uF  [C0603]
C388  10uF  [C0603]
C638  0.1uF  [C0402]
C639  22uF  [C0603]
C640  22uF  [C0603]
C641  10uF  [C0603]
C642  22uF  [C0603]
C643  22uF  [C0603]
C644  10uF  [C0603]
C645  0.1uF  [C0402]
C646  22uF  [C0603]
C647  22uF  [C0603]
C648  10uF  [C0603]
C649  0.1uF  [C0402]
C650  22uF  [C0603]
C651  22uF  [C0603]
C652  10uF  [C0603]
C653  0.1uF  [C0402]
C654  22uF  [C0603]
C655  22uF  [C0603]
C656  10uF  [C0603]
C657  0.1uF  [C0402]
C658  0.1uF  [C0402]
C659  22uF  [C0603]
C660  22uF  [C0603]
C661  10uF  [C0603]
C662  0.1uF  [C0402]
C663  22uF  [C0603]
C664  22uF  [C0603]
C665  10uF  [C0603]
C734  0.1uF-DNI  [C0402]
D61  1V00  [APT1608]
D63  1V10  [APT1608]
D64  1V80  [APT1608]
D65  1V20  [APT1608]
D66  2V50  [APT1608]
D67  1V50  [APT1608]
D68  0V90  [APT1608]
D69  1V35  [APT1608]
L5  3.3uH  [SRP4020TA-3R3M]
L8  1.5uH  [SRP4020TA-1R5M]
L15  1.5uH  [SRP4020TA-1R5M]
L16  2.2uH  [SRP4020TA-2R2M]
L17  3.3uH  [SRP4020TA-3R3M]
L18  2.2uH  [SRP4020TA-2R2M]
L19  1uH  [SMD]
L20  2.2uH  [SRP4020TA-2R2M]
Q7  BC817-40-TP  [SOT23-3]
Q8  BC817-40-TP  [SOT23-3]
Q9  BC817-40-TP  [SOT23-3]
Q10  BC817-40-TP  [SOT23-3]
Q11  BC817-40-TP  [SOT23-3]
Q12  BC817-40-TP  [SOT23-3]
Q13  BC817-40-TP  [SOT23-3]
Q14  BC817-40-TP  [SOT23-3]
R169  330R  [R0603]
R185  4.7k  [R0603]
R189  0  [R0603]
R192  10K-DNI  [R0402]
R229  10K  [R0603]
R231  2.61K  [0603]
R232  10K  [R0603]
R233  18.2 k  [res0402]
R234  12.7 k  [res0402]
R287  19.1K  [R0603]
R288  19.1K-DNI  [R0603]
R416  10K  [R0603]
R417  330R  [R0603]
R418  18.2 k  [res0402]
R419  12.7 k  [res0402]
R420  3.83K  [0603]
R421  10K  [R0603]
R424  10K  [R0603]
R425  12.7 K  [res0402]
R426  10K  [R0603]
R427  330R  [R0603]
R428  18.2 k  [res0402]
R429  12.7 k  [res0402]
R430  10K  [R0603]
R431  5.11K  [0603]
R432  10K  [R0603]
R433  330R  [R0603]
R434  18.2 k  [res0402]
R435  12.7 k  [res0402]
R436  10K  [R0603]
R437  21.5K  [0603]
R438  10K  [R0603]
R439  330R  [R0603]
R440  12.7 k  [res0402]
R441  18.2 k  [res0402]
R442  10K  [R0603]
R443  10K  [R0603]
R444  330R  [R0603]
R445  8.87K  [0603]
R446  10K  [R0603]
R447  330R  [R0603]
R448  18.2 k  [res0402]
R449  12.7 k  [res0402]
R450  1.33K  [0603]
R451  10K  [R0603]
R452  10K  [R0603]
R453  330R  [R0603]
R454  18.2 k  [res0402]
R455  12.7 k  [res0402]
R456  6.98K  [0603]
R457  10K  [R0603]
R572  10K  [R0402]
R577  0  [R0402]
R716  0-DNI  [R0402]
U17  AP62201WU-7  [TSOT26_AP62201WU-7]
U35  AP62201WU-7  [TSOT26_AP62201WU-7]
U36  AP62201WU-7  [TSOT26_AP62201WU-7]
U37  AP62201WU-7  [TSOT26_AP62201WU-7]
U38  AP62201WU-7  [TSOT26_AP62201WU-7]
U39  AP62201WU-7  [TSOT26_AP62201WU-7]
U40  AP62201WU-7  [TSOT26_AP62201WU-7]
U41  AP62201WU-7  [TSOT26_AP62201WU-7]
U116  RP115H181D-T1-FE  [SOT89-5]

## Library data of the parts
GND1-GND5 = TP_S_40_63: Assy: DNI
J31-J33 J81 = HEADER_1: BOM1_Sensor_Population: POPULATE; BOM2_DUT_Population: DNP; Man. Part #: 1573-2; Manufacturer: Keystone Electronics
J58-J60 J63-J73 J76-J80 = J-Header_2x1
JP31-JP36 JP47-JP50 JP58-JP62 JP69-JP78 = J-2_Pin_Jumper: Manufacturer Part Number: 22-28-4020
R137 R139 R140 R142 R143 R147 R353 R370 R374 R378 R387 R391 R395 R714 = R0603_0.01_1%_Yageo: Manufacturer Part Number: PF0603FRE7T0R01Z
R536 R657 = R: RES SMD 0.0OHM JUMPER 1/10W 0402; COMPFIXED: NO; COMPHEIGHT: 0.000; COMPKEY: NO; COMPLOC: [3325.000,1400.000]; COMPLOCKED: NO; COMPROT: 180; COMPSIDE: TOP; DECOUPLER: NO; FPLIST: AX/RC05; MEMORY: NO; Manufacturer: Panasonic; Manufacturer Part Number: ERJ-2GE0R00X
VCCAPLL4 VCCAPLL7 VCCAPLL10 VCCAPLLW VCCAUX VCCIO0-VCCIO14 VCCORE = T_POINT_R: Assy: DNI
C465 C467 C468 C470 C472 C473 C475-C482 C484 C486 C487 C489-C509 C511 C1222 C1224 C1226 C1228-C1254 C1256 C1665 = C-0201_0.1uF_100V_X5R_MURATA: CAP CER 0.1UF 10V X5R 0201; MFG P/N: GRM033R61A104KE15D; Manufacturer: Murata Electronics; Manufacturer Part No: GRM033R61A104KE15D; Manufacturer Part Number: GRM033R61A104KE15D
C36 C396 C397 C466 C469 C471 C474 C483 C485 C488 C510 C512 C525 C631 C1221 C1223 C1225 C1227 C1255 C1257 = C-0402_10U_6.3V_X5R_TDK: Manufacturer: TDK Corporation; Manufacturer Part No: C1005X5R0J106M050BC; Manufacturer Part Number: C1005X5R0J106M050BC
C31 C32 C526 C527 C529 C530 C542 C545 C546 C548 C592-C594 C599 C600 = 0u1_0402: CAP CER 0.1UF 25V 10% X5R 0201; Manufacturer: Murata; Manufacturer Part Number: GRM033R61E104KE14J
C33 C528 C547 C591 C619 = 10uF_0603
C385 C632 C638 C645 C649 C653 C657 C658 C662 = C_0.1uF_50V_CER_0402: Manufacturer Part Number: GRM155R71H104KE14J
FB28 FB29 = FB__220E_0603
JP83-JP86 = 3-PINS_0.1_SINGLE_LINE_PIN
R290 R294 R685 = R0402_240_5%_YAGEO: RES 240 OHM 1% 1/20W 0201; MFG P/N: RC0201FR-07240RL; Manufacturer: Yageo; Manufacturer Part No: RC0201FR-07240RL; Manufacturer Part Number: RC0201FR-07240RL
R291 R633 = R0402_240_5%_YAGEO: Manufacturer: Yageo; Manufacturer Part No: RC0402JR-07240RL; Manufacturer Part Number: RC0402JR-07240RL
R292 R293 R596-R598 R644-R647 = R: RES SMD 4.7K OHM 1% 1/16W 0402; DECOUPLER: NO; Digikey P/N: 311-4.7KLRTR-ND; MEMORY: NO; Manufacturer: Yageo; Manufacturer Part No: RC0402FR-074K7L; Manufacturer Part Number: RC0402FR-074K7L
R490 R491 = R0201_49R9_1%_YAGEO: Manufacturer Part Number: RC0201FR-0749R9L
R492 R493 = R0402_0R_NP_5%_PANASONIC: RES SMD 0 OHM JUMPER 1/20W 0201; MFG: Vishay Dale; MFG P/N: CRCW02010000Z0ED; Manufacturer Part Number: CRCW02010000Z0ED
R537 R538 R548 = R0402_0R_5%_PANASONIC: RES SMD 0 OHM JUMPER 1/20W 0201; MFG: Vishay Dale; MFG P/N: CRCW02010000Z0ED; Manufacturer Part Number: CRCW02010000Z0ED
R582 R636 = R0402_100_1%_YAGEO
U5 U119 = IC_MT53E128M32D2DS-053_200FBGA: Manufacturer Part Number: MT53E128M32D2DS-053 WT:A
Y1 = Y_100_Mhz_HCSL: Manufacturer Part Number: AX3HAF1-100.0000
J6 J7 = SKT2x6_PPPC062LFBN-RC: CONN HDR 12POS 0.1 GOLD PCB R/A; Manufacturer: Sullins
J23 J57 = Header_2x1
R82 R298 = R0402_0.01R_1%_YAGEO: Manufacturer Part Number: PE0402FRF070R01L
R345 = R_v2: RES SMD 33 OHM 1% 1/10W 0402; Manufacturer: Panasonic; Manufacturer Part Number: ERJ-2RKF33R0X
U3 = LAV-AT-E70-LFG1156_6
D60 = 7SEG_LDT-N2804RI__12-DIP
JP12 JP13 = JUMPER_0
JP26 = Receptacle_20X2
Q2-Q4 = TRANS_NPN_45V_0_0.8A_SOT-23: TRANS NPN 45V 0.8A SOT-23
R103-R108 = 0R_0603: RES 0.0 OHM 1/10W JUMP 0603 SMD; Assy: DNI
R331-R338 = R_53.6R_0402: Manufacturer Part Number: RC0402FR-0753R6L
R169 R339 R341 R343 R417 R427 R433 R439 R444 R447 R453 = R_330R_0603: Manufacturer Part Number: ERJ-3EKF3300V
R340 R342 R344 = R_4.7K_0603: Manufacturer Part Number: RC0603JR-074K7L
C138-C140 C163 C168 C169 C402 C403 C405 = CAP_NP: COMPFIXED: NO; COMPGROUP: 0; COMPHEIGHT: 0.000; COMPKEY: NO; COMPLOC: [1820.000,2015.000]; COMPLOCKED: NO; COMPROT: 270; COMPSIDE: TOP; DECOUPLER: NO; FPLIST: SM/C_0402; MEMORY: NO
C142-C152 C164-C167 C171-C174 C176-C178 C289-C292 C398-C401 C404 = CAP_1: CAP CER 0.1UF 25V 10% X5R 0201; Manufacturer: Murata; Manufacturer Part Number: GRM033R61E104KE14J
C175 = CAP_SMT_0805: CAP CER 0.1UF 25V 10% X5R 0201; Manufacturer: Murata; Manufacturer Part Number: GRM033R61E104KE14J
C287 C288 C293 C717 = C-0402_10nF_6.3V_X5R_MURATA: Manufacturer Part Number: GRM155R60J103KA01D
C612 C613 = C-0402_22uF_X5R_6V3_Kyocera: Manufacturer Part Number: CM05X5R226M06AH080
FB16 = INDUCTOR_0: FERRITE BEAD 120 OHM 0402 1LN; Manufacturer: TDK Corporation
FB22 FB25-FB27 = FB_0402_600R_Murata
R154 = R0603_0R1_1%_VishayDale
R267 R539-R541 = R0603_1R_1%_Panasonic_1_4W
R658 = RES_2: SMD 0.002ohms 0.1% 3w; ALT_SYMBOLS: RESC100X50X40RND; Agile Part Number: RES-00035-01; Barcode: 200067; CIP Link: http://xsjbrdwin1/CIP-E/Component/Index/All?pn=200067; Manufacturer: Vishay Precision Group; Manufacturer Part Number: Y14880R00200B9R; OWNER: 3670; PRICE: 0.01; Part Number: Y14880R00200B9R; Part Type: SMT - 1%; PartType: SMT - 1%; Power: 1/16W; ROHS: Yes; Rated Power: 1/16W; Tolerance: 0.1%; primarykey: 128
C94 = 0u1_0402
C207 C208 = 10uF_0603: Voltage: 16V
C386 C387 C639 C640 C642 C643 C646 C647 C650 C651 C654 C655 C659 C660 C663 C664 = C-0603_22uF_10V_X5R_Samsung: Manufacturer Part Number: CL10A226MP8NUNE
C388 C641 C644 C648 C652 C656 C661 C665 = C_10uf_CER_25V_0603: CAP CER 10UF 25V X5R 0805; Manufacturer: TDK Corporation; Manufacturer Part No: C2012X5R1E106M085AC; Manufacturer Part Number: C2012X5R1E106M085AC
C734 = C-0402_0.1uF_6.3V_X5R_MURATA_NP
D61 D63-D69 = LED_GREEN_0: Manufacturer Part Number: SML-D12M8WT86
L5 L17 = INDUCTOR_0: FIXED IND 3.3UH 3.5A 76 MOHM SMD; Manufacturer: Bourns Inc.
L8 L15 = INDUCTOR_0: FIXED IND 1.5UH 4.5A 42 MOHM SMD; Manufacturer: Bourns Inc.
L16 L18 L20 = INDUCTOR_0: FIXED IND 2.2UH 4A 61 MOHM SMD; Manufacturer: Bourns Inc.
L19 = L-1uH_BOURNS: Manufacturer Part Number: SRP4020TA-1R0M
Q7-Q14 = TRANS_NPN_45V_0_0.8A_SOT-23: TRANS NPN 45V 0.8A SOT-23; Manufacturer: Micro Commercial Co
R185 = 5k1_0402: RES SMD 4.7K OHM 1% 1/10W 0402; MFG: VISHAY; MFG P/N: CRCW06034K70FKEA; Manufacturer: Panasonic; Manufacturer Part Number: ERJ-2RKF4701X
R189 = 0R_0603: RES SMD 0.0OHM JUMPER 1/10W 0402; Manufacturer: Panasonic; Manufacturer Part Number: ERJ-2GE0R00X
R192 = 5k1_0402: RES SMD 2.2K OHM 1% 1/10W 0402; Digikey P/N: 311-2.20KLRTR-ND; Manufacturer: Panasonic; Manufacturer Part Number: ERJ-2RKF2201X
R229 R416 R426 R432 R438 R443 R446 R452 = R_10K_0603: Manufacturer Part Number: RC1608F103CS
R231 = R0603_2K61_1%_Yageo
R232 R421 R424 R430 R436 R442 R451 R457 = R0603_10K_1%_Yageo: Manufacturer Part Number: RC0603FR-0710KL
R233 R418 R428 R434 R441 R448 R454 = R_42.2K_0402: RES SMD 18.2KOHM 0.1% 1/16W 0402; Manufacturer: YAGEO; Manufacturer Part No: RT0402BRD0718K2L; Manufacturer Part Number: RT0402BRD0718K2L
R234 R419 R429 R435 R440 R449 R455 = R_12.7K_0402: Manufacturer Part Number: ERJ-2RKF1272X
R287 R288 = R0603_19K1_1%_Yageo
R420 = R0603_3K83_1%_Yageo
R425 = R0603_12K7_1%_Yageo
R431 = R0603_5K11_1%_Yageo
R437 = R0603_21K5_1%_Yageo
R445 = R0603_8K87_1%_Yageo
R450 = R0603_1K33_1%_Yageo
R456 = R0603_6K98_1%_Yageo
R572 = R0402_10K_5%_VISHAY
R577 = R0402_0R_5%_PANASONIC
R716 = 0R_0603: Thick Film Resistors - SMD 0402 Zero Ohms; Manufacturer: Vishay / Dale; Manufacturer Part Number: CRCW04020000ZSTD; Part Number: Part Number
U17 U35-U41 = U-AP62201WU-7
U116 = RP111HXX1D

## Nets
1V8_LDO: C208.1 FB16.1 FB28.1 R189.2 U116.5(Vout)
1V80_EN: R716.2 ; also on sheet 19
1V80_MON: R577.2 ; also on sheet 19
1V80_TRIM: R287.2 ; also on sheet 19
GND: C31.2 C32.2 C33.2 C36.2 C94.2 C138.1 C139.1 C140.1 C142.2 C143.2 C144.2 C145.2 C146.2 C147.2 C148.2 C149.2 C150.2 C151.2 C152.2 C163.1 C164.2 C165.2 C166.2 C167.2 C168.1 C169.1 C171.2 C172.2 C173.2 C174.2 C175.2 C176.2 C177.2 C178.2 C207.2 C208.2 C287.2 C288.2 C289.2 C290.2 C291.2 C292.2 C293.2 C386.2 C387.2 C388.2 C396.2 C397.2 C398.2 C399.2 C400.2 C401.2 C402.1 C403.1 C404.2 C405.1 C465.2 C466.2 C467.2 C468.2 C469.2 C470.2 C471.2 C472.2 C473.2 C474.2 C475.2 C476.2 C477.2 C478.2 C479.2 C480.2 C481.2 C482.2 C483.2 C484.2 C485.2 C486.2 C487.2 C488.2 C489.2 C490.2 C491.2 C492.2 C493.2 C494.2 C495.2 C496.2 C497.2 C498.2 C499.2 C500.2 C501.2 C502.2 C503.2 C504.2 C505.2 C506.2 C507.2 C508.2 C509.2 C510.2 C511.2 C512.2 C525.2 C526.2 C527.2 C528.2 C529.2 C530.2 C542.2 C545.2 C546.2 C547.2 C548.2 C591.2 C592.2 C593.2 C594.2 C599.2 C600.2 C612.2 C613.2 C619.2 C631.2 C632.2 C639.2 C640.2 C641.2 C642.2 C643.2 C644.2 C646.2 C647.2 C648.2 C650.2 C651.2 C652.2 C654.2 C655.2 C656.2 C659.2 C660.2 C661.2 C663.2 C664.2 C665.2 C717.2 C734.2 C1221.2 C1222.2 C1223.2 C1224.2 C1225.2 C1226.2 C1227.2 C1228.2 C1229.2 C1230.2 C1231.2 C1232.2 C1233.2 C1234.2 C1235.2 C1236.2 C1237.2 C1238.2 C1239.2 C1240.2 C1241.2 C1242.2 C1243.2 C1244.2 C1245.2 C1246.2 C1247.2 C1248.2 C1249.2 C1250.2 C1251.2 C1252.2 C1253.2 C1254.2 C1255.2 C1256.2 C1257.2 GND1.1(TP) GND2.1(TP) GND3.1(TP) GND4.1(TP) GND5.1(TP) J6.5 J6.11 J7.5 J7.11 J31.1 J32.1 J33.1 J81.1 JP26.6 JP26.9 JP26.14 JP26.20 JP26.25 JP26.30 JP26.34 JP26.39 Q2.E Q3.E Q4.E Q7.E Q8.E Q9.E Q10.E Q11.E Q12.E Q13.E Q14.E R192.1 R232.2 R234.2 R340.2 R342.2 R344.2 R419.2 R421.2 R424.2 R429.2 R430.2 R435.2 R436.2 R440.2 R442.2 R449.2 R451.2 R455.2 R457.2 R493.1 R548.1 R596.2 R597.1 R598.1 R644.1 R645.1 U5.A3(VSS) U5.A10(VSS) U5.AB3(VSS) U5.AB5(VSS) U5.AB8(VSS) U5.AB10(VSS) U5.C1(VSS) U5.C5(VSS) U5.C8(VSS) U5.C12(VSS) U5.D2(VSS) U5.D4(VSS) U5.D9(VSS) U5.D11(VSS) U5.E1(VSS) U5.E5(VSS) U5.E8(VSS) U5.E12(VSS) U5.G1(VSS) U5.G3(VSS) U5.G5(VSS) U5.G8(VSS) U5.G10(VSS) U5.G12(VSS) U5.J1(VSS) U5.J3(VSS) U5.J10(VSS) U5.J12(VSS) U5.K2(VSS) U5.K4(VSS) U5.K9(VSS) U5.K11(VSS) U5.N2(VSS) U5.N4(VSS) U5.N9(VSS) U5.N11(VSS) U5.P1(VSS) U5.P3(VSS) U5.P10(VSS) U5.P12(VSS) U5.T1(VSS) U5.T3(VSS) U5.T5(VSS) U5.T8(VSS) U5.T10(VSS) U5.T12(VSS) U5.V1(VSS) U5.V5(VSS) U5.V8(VSS) U5.V12(VSS) U5.W2(VSS) U5.W4(VSS) U5.W9(VSS) U5.W11(VSS) U5.Y1(VSS) U5.Y5(VSS) U5.Y8(VSS) U5.Y12(VSS) U17.1(GND) U35.1(GND) U36.1(GND) U37.1(GND) U38.1(GND) U39.1(GND) U40.1(GND) U41.1(GND) U116.2(GND) U119.A3(VSS) U119.A10(VSS) U119.AB3(VSS) U119.AB5(VSS) U119.AB8(VSS) U119.AB10(VSS) U119.C1(VSS) U119.C5(VSS) U119.C8(VSS) U119.C12(VSS) U119.D2(VSS) U119.D4(VSS) U119.D9(VSS) U119.D11(VSS) U119.E1(VSS) U119.E5(VSS) U119.E8(VSS) U119.E12(VSS) U119.G1(VSS) U119.G3(VSS) U119.G5(VSS) U119.G8(VSS) U119.G10(VSS) U119.G12(VSS) U119.J1(VSS) U119.J3(VSS) U119.J10(VSS) U119.J12(VSS) U119.K2(VSS) U119.K4(VSS) U119.K9(VSS) U119.K11(VSS) U119.N2(VSS) U119.N4(VSS) U119.N9(VSS) U119.N11(VSS) U119.P1(VSS) U119.P3(VSS) U119.P10(VSS) U119.P12(VSS) U119.T1(VSS) U119.T3(VSS) U119.T5(VSS) U119.T8(VSS) U119.T10(VSS) U119.T12(VSS) U119.V1(VSS) U119.V5(VSS) U119.V8(VSS) U119.V12(VSS) U119.W2(VSS) U119.W4(VSS) U119.W9(VSS) U119.W11(VSS) U119.Y1(VSS) U119.Y5(VSS) U119.Y8(VSS) U119.Y12(VSS) Y1.3(GND) ; also on sheet 3 4 5 6 7 8 9 10 17 18 19 20
VCC_0V82: J73.1 R658.3(I1) ; also on sheet 8 17
VCC_0V90: C659.1 C660.1 JP31.1 L19.2 R446.2 R450.1 ; also on sheet 8
VCC_1V00: C386.1 C387.1 JP32.1 L8.2 R229.2 R231.1 ; also on sheet 8
VCC_1V10: C639.1 C640.1 FB29.1 JP33.1 L15.2 R416.2 R420.1 R492.2 ; also on sheet 8
VCC_1V20: C646.1 C647.1 JP47.1 JP58.1 JP59.1 JP60.1 JP61.1 JP62.1 L16.2 R431.1 R432.2 ; also on sheet 8 17
VCC_1V35: C663.1 C664.1 JP34.1 L20.2 R452.2 R456.1 ; also on sheet 8
VCC_1V50: C654.1 C655.1 JP35.1 L18.2 R443.2 R445.1 R714.2 ; also on sheet 8
VCC_1V80: C642.1 C643.1 JP36.1 JP48.1 JP69.1 JP71.1 JP73.1 JP75.1 JP77.1 L5.2 R425.1 R426.2 R577.1 ; also on sheet 8 19
VCC_2V50: C207.1 C650.1 C651.1 JP49.1 L17.2 R185.1 R437.1 R438.2 U116.4(Vdd) ; also on sheet 8
VCC_3V30: C632.1 J58.1 J63.1 J64.1 JP12.1 JP50.1 R139.1 R169.2 R391.1 R395.1 R417.2 R427.2 R433.2 R439.2 R444.2 R447.2 R453.2 R536.2 R657.2 Y1.1(E/D) Y1.6(VDD) ; also on sheet 3 7 8 10 17
VCC_5V00: C388.1 C641.1 C644.1 C648.1 C652.1 C656.1 C661.1 C665.1 JP13.1 R233.1 R418.1 R428.1 R434.1 R441.1 R448.1 R454.1 R572.1 U17.3(VIN) U35.3(VIN) U36.3(VIN) U37.3(VIN) U38.3(VIN) U39.3(VIN) U40.3(VIN) U41.3(VIN) ; also on sheet 8 17
VCC_AUX: C396.1 C397.1 C398.1 C399.1 C400.1 C401.1 J76.1 R154.1 U3.P11(VCCAUXA) U3.W18(VCCAUX) U3.Y12(VCCAUX) U3.Y22(VCCAUX) VCCAUX.1(TP)
VCC_AUX_IN: FB16.2 J76.2 R154.2
VCC_CORE: C138.2 C139.2 C140.2 C142.1 C143.1 C144.1 C145.1 C146.1 C147.1 C148.1 C149.1 C150.1 C151.1 C152.1 C163.2 C164.1 C165.1 C166.1 C167.1 C168.2 C169.2 C171.1 C172.1 C173.1 C174.1 C175.1 C176.1 C177.1 C178.1 C402.2 C403.2 C404.1 C405.2 C612.1 C613.1 J73.2 R658.4(I2) U3.AA12(VCC) U3.AA22(VCC) U3.N21(VCC) U3.N22(VCC) U3.N24(VCC) U3.P21(VCC) U3.R20(VCC) U3.R22(VCC) U3.R24(VCC) U3.T20(VCC) U3.T22(VCC) U3.U13(VCC) U3.U19(VCC) U3.U21(VCC) U3.V17(VCC) U3.V19(VCC) U3.V21(VCC) U3.W13(VCC) U3.W15(VCC) U3.W17(VCC) U3.W20(VCC) U3.Y14(VCC) U3.Y15(VCC) U3.Y19(VCC) VCCORE.1(TP) ; also on sheet 17
VCC_DDR: C466.1 C467.1 C469.1 C470.1 C471.1 C472.1 C474.1 C475.1 C477.1 C479.1 C481.1 C482.1 C484.1 C486.1 C490.1 C492.1 C495.1 C498.1 C499.1 C500.1 C501.1 C502.1 C503.1 C504.1 C505.1 C506.1 C508.1 C511.1 C1221.1 C1222.1 C1223.1 C1224.1 C1225.1 C1226.1 C1227.1 C1228.1 C1229.1 C1230.1 C1231.1 C1232.1 C1233.1 C1235.1 C1238.1 C1240.1 C1242.1 C1245.1 C1246.1 C1247.1 C1248.1 C1249.1 C1250.1 C1251.1 C1252.1 C1253.1 C1254.1 C1256.1 FB29.2 J70.1 R291.1 R292.2 R293.2 R374.1 R633.1 R646.2 R647.2 U5.A4(VDD2) U5.A9(VDD2) U5.AA3(VDDQ) U5.AA5(VDDQ) U5.AA8(VDDQ) U5.AA10(VDDQ) U5.AB4(VDD2) U5.AB9(VDD2) U5.B3(VDDQ) U5.B5(VDDQ) U5.B8(VDDQ) U5.B10(VDDQ) U5.D1(VDDQ) U5.D5(VDDQ) U5.D8(VDDQ) U5.D12(VDDQ) U5.F3(VDDQ) U5.F5(VDD2) U5.F8(VDD2) U5.F10(VDDQ) U5.H1(VDD2) U5.H5(VDD2) U5.H8(VDD2) U5.H12(VDD2) U5.K1(VDD2) U5.K3(VDD2) U5.K10(VDD2) U5.K12(VDD2) U5.N1(VDD2) U5.N3(VDD2) U5.N10(VDD2) U5.N12(VDD2) U5.R1(VDD2) U5.R5(VDD2) U5.R8(VDD2) U5.R12(VDD2) U5.U3(VDDQ) U5.U5(VDD2) U5.U8(VDD2) U5.U10(VDDQ) U5.W1(VDDQ) U5.W5(VDDQ) U5.W8(VDDQ) U5.W12(VDDQ) U119.A4(VDD2) U119.A9(VDD2) U119.AA3(VDDQ) U119.AA5(VDDQ) U119.AA8(VDDQ) U119.AA10(VDDQ) U119.AB4(VDD2) U119.AB9(VDD2) U119.B3(VDDQ) U119.B5(VDDQ) U119.B8(VDDQ) U119.B10(VDDQ) U119.D1(VDDQ) U119.D5(VDDQ) U119.D8(VDDQ) U119.D12(VDDQ) U119.F3(VDDQ) U119.F5(VDD2) U119.F8(VDD2) U119.F10(VDDQ) U119.H1(VDD2) U119.H5(VDD2) U119.H8(VDD2) U119.H12(VDD2) U119.K1(VDD2) U119.K3(VDD2) U119.K10(VDD2) U119.K12(VDD2) U119.N1(VDD2) U119.N3(VDD2) U119.N10(VDD2) U119.N12(VDD2) U119.R1(VDD2) U119.R5(VDD2) U119.R8(VDD2) U119.R12(VDD2) U119.U3(VDDQ) U119.U5(VDD2) U119.U8(VDD2) U119.U10(VDDQ) U119.W1(VDDQ) U119.W5(VDDQ) U119.W8(VDDQ) U119.W12(VDDQ)
VCC_DDR_VDD1: C487.1 C489.1 C491.1 C493.1 C494.1 C496.1 C497.1 C510.1 C512.1 C1234.1 C1236.1 C1237.1 C1239.1 C1241.1 C1243.1 C1244.1 C1255.1 C1257.1 FB28.2 U5.F1(VDD1) U5.F12(VDD1) U5.G4(VDD1) U5.G9(VDD1) U5.T4(VDD1) U5.T9(VDD1) U5.U1(VDD1) U5.U12(VDD1) U119.F1(VDD1) U119.F12(VDD1) U119.G4(VDD1) U119.G9(VDD1) U119.T4(VDD1) U119.T9(VDD1) U119.U1(VDD1) U119.U12(VDD1)
VCCA_PLL4: C287.1 C289.1 J79.1 R540.1 U3.AA13(VCCA_PLL4) VCCAPLL4.1(TP)
VCCA_PLL4_IN: FB26.1 J79.2 R540.2
VCCA_PLL7: C292.1 C717.1 J80.1 R541.1 U3.Y16(VCCA_PLL7) VCCAPLL7.1(TP)
VCCA_PLL7_IN: FB27.1 J80.2 R541.2
VCCA_PLL10: C290.1 C293.1 J78.1 R539.1 U3.AA23(VCCA_PLL10) VCCAPLL10.1(TP)
VCCA_PLL10_IN: FB25.1 J78.2 R539.2
VCCA_PLLW: C288.1 C291.1 J77.1 R267.1 U3.P12(VCCA_PLL_W) VCCAPLLW.1(TP)
VCCA_PLLW_IN: FB22.1 J77.2 R267.2
VCCBAT_1V50: R714.1 U3.M16(VCC_BAT)
VCCIO0: J58.2 R139.2 VCCIO0.1(TP) ; also on sheet 4
VCCIO1: J59.2 R143.1 VCCIO1.1(TP) ; also on sheet 4
VCCIO1_IN: J59.1 R143.2 R536.1 ; also on sheet 4
VCCIO2: J60.2 R140.2 VCCIO2.1(TP) ; also on sheet 5
VCCIO2_IN: J60.1 R140.1 R657.1 ; also on sheet 5
VCCIO3: J65.2 R137.2 VCCIO3.1(TP) ; also on sheet 6
VCCIO3_IN: J65.1 JP60.2 JP69.2 JP70.2 R137.1
VCCIO4: J66.2 R142.2 VCCIO4.1(TP) ; also on sheet 6
VCCIO4_IN: J66.1 JP59.2 JP71.2 JP72.2 R142.1
VCCIO5: J67.2 R147.2 VCCIO5.1(TP) ; also on sheet 6
VCCIO5_IN: J67.1 JP58.2 JP73.2 JP74.2 R147.1
VCCIO6: J71.2 R353.2 VCCIO6.1(TP) ; also on sheet 8
VCCIO6_IN: J71.1 JP31.2 JP32.2 JP33.2 JP34.2 JP35.2 JP36.2 R353.1 ; also on sheet 8
VCCIO7: J68.2 R378.2 VCCIO7.1(TP) ; also on sheet 9
VCCIO7_IN: J68.1 JP61.2 JP75.2 JP76.2 R378.1
VCCIO8: J69.2 R370.2 VCCIO8.1(TP) ; also on sheet 9
VCCIO8_IN: J69.1 JP62.2 JP77.2 JP78.2 R370.1
VCCIO10: C465.1 C468.1 C473.1 C476.1 C478.1 C480.1 C483.1 C485.1 C488.1 C507.1 C509.1 C542.1 C545.1 C546.1 C547.1 C548.1 C619.1 C631.1 J70.2 R290.2 R294.2 R374.2 R685.2 U3.AA25(VCCIO11) U3.AB22(VCCIO10) U3.AC28(VCCIO10) U3.AC31(VCCIO10) U3.AD24(VCCIO10) U3.AH27(VCCIO9) U3.AH31(VCCIO9) U3.AL31(VCCIO9) U3.AP33(VCCIO9) U3.V23(VCCIO11) U3.W27(VCCIO11) U3.W31(VCCIO11) VCCIO9.1(TP) VCCIO10.1(TP) VCCIO11.1(TP)
VCCIO12: C31.1 C32.1 C33.1 C526.1 J72.2 R387.2 U3.M14(VCCIO12) U3.N18(VCCIO12) U3.P16(VCCIO12) VCCIO12.1(TP)
VCCIO12_IN: J23.1 J57.1 J72.1 JP47.2 JP48.2 JP49.2 JP50.2 R82.1 R298.1 R387.1
VCCIO13: C527.1 C528.1 C529.1 C530.1 J63.2 R391.2 U3.M13(VCCIO13) U3.T14(VCCIO13) U3.T16(VCCIO13) VCCIO13.1(TP)
VCCIO14: C591.1 C592.1 C593.1 C594.1 J64.2 R395.2 U3.N12(VCCIO14) U3.U9(VCCIO14) U3.U11(VCCIO14) VCCIO14.1(TP)
VCCPLL_0V82: FB22.2 FB25.2 FB26.2 FB27.2 ; also on sheet 17
F_DDR_100MHz_N: R491.2 R538.1 U3.AD31(HPIO10_13B/PLLC10_IN/DP2_PLLC10_IN)
F_DDR_100MHz_P: R490.1 R537.1 U3.AD32(HPIO10_13A/PLLT10_IN/DP2_PLLT10_IN)
F_K_DIG1: R343.1 U3.W9(WRIO14_4A)
F_K_DIG2: R339.1 U3.V9(WRIO14_4B)
F_K_DIG3: R341.1 U3.R10(WRIO14_9B)
FMC2_PG_C2M: U3.T18(WRIO13_2A) ; also on sheet 10
FMC2_PG_M2C: U3.T19(WRIO13_2B) ; also on sheet 10
FMC2_PRSNT_M2C_L: U3.T15(WRIO13_3A) ; also on sheet 10
FMC2_RES0: U3.R19(WRIO13_0A) ; also on sheet 10
FMC2_RES1: U3.R18(WRIO13_0B) ; also on sheet 10
FMC2_SCL: U3.R15(WRIO13_1B) ; also on sheet 10
FMC2_SDA: U3.R14(WRIO13_1A) ; also on sheet 10
FMC2_TCK: R345.1 ; also on sheet 10
FMC2_TDI: U3.U16(WRIO13_4A) ; also on sheet 10
FMC2_TDO: U3.U17(WRIO13_4B) ; also on sheet 10
FMC2_TMS: U3.W14(WRIO13_5A) ; also on sheet 10
IMON1N_082V: R658.2(V2) ; also on sheet 19
IMON1P_082V: R658.1(V1) ; also on sheet 19
K_DIG1: D60.12(K_DIG1) Q4.C
K_DIG2: D60.9(K_DIG2) Q2.C
K_DIG3: D60.8(K_DIG3) Q3.C
LPDDR4_A0_A: U3.AC26(HPIO10_2B/DP2_MA0) U5.H2(CA0_A) U5.R2(CA0_B) U119.H2(CA0_A) U119.R2(CA0_B)
LPDDR4_A1_A: U3.AB27(HPIO10_4A/DP2_MA1) U5.J2(CA1_A) U5.P2(CA1_B) U119.J2(CA1_A) U119.P2(CA1_B)
LPDDR4_A2_A: U3.AB28(HPIO10_4B/DP2_MA2) U5.H9(CA2_A) U5.R9(CA2_B) U119.H9(CA2_A) U119.R9(CA2_B)
LPDDR4_A3_A: U3.AC29(HPIO10_6A/DP2_MA3) U5.H10(CA3_A) U5.R10(CA3_B) U119.H10(CA3_A) U119.R10(CA3_B)
LPDDR4_A4_A: U3.AB29(HPIO10_6B/DP2_MA4) U5.H11(CA4_A) U5.R11(CA4_B) U119.H11(CA4_A) U119.R11(CA4_B)
LPDDR4_A5_A: U3.AD27(HPIO10_8A/DP2_MA5) U5.J11(CA5_A) U5.P11(CA5_B) U119.J11(CA5_A) U119.P11(CA5_B)
LPDDR4_CKE_A: U3.AB26(HPIO10_2A/DP2_CKE0) U5.J4(CKE0_A) U5.P4(CKE0_B) U119.J4(CKE0_A) U119.P4(CKE0_B)
LPDDR4_CLK_A_N: C1665.1 R582.1 R636.1 U3.AC25(HPIO10_0B/DP2_MCLKC0) U5.J9(CK_C_A) U5.P9(CK_C_B) U119.J9(CK_C_A) U119.P9(CK_C_B)
LPDDR4_CLK_A_P: C1665.2 R582.2 R636.2 U3.AB25(HPIO10_0A/DP2_MCLKT0) U5.J8(CK_T_A) U5.P8(CK_T_B) U119.J8(CK_T_A) U119.P8(CK_T_B)
LPDDR4_CS_A: U3.AA31(HPIO10_7A/DP2_CS_N0) U5.H4(CS0_A) U5.R4(CS0_B) U119.H4(CS0_A) U119.R4(CS0_B)
LPDDR4_DQ0_A: U3.AD22(HPIO10_20B/DP2_DQ00) U5.B2(DQ0_A)
LPDDR4_DQ0_B: U3.U29(HPIO11_3A/DP2_DQ16) U5.AA2(DQ0_B)
LPDDR4_DQ0_C: U3.V28(HPIO11_2A/DP2_DQ32) U119.B2(DQ0_A)
LPDDR4_DQ0_D: U3.AK32(HPIO9_7B/DP2_DQ48) U119.AA2(DQ0_B)
LPDDR4_DQ1_A: U3.AD21(HPIO10_20A/DP2_DQ01) U5.C2(DQ1_A)
LPDDR4_DQ1_B: U3.V29(HPIO11_3B/DP2_DQ17) U5.Y2(DQ1_B)
LPDDR4_DQ1_C: U3.U28(HPIO11_2B/DP2_DQ33) U119.C2(DQ1_A)
LPDDR4_DQ1_D: U3.AK31(HPIO9_7A/DP2_DQ49) U119.Y2(DQ1_B)
LPDDR4_DQ2_A: U3.AE25(HPIO10_14B/DP2_DQ02) U5.E2(DQ2_A)
LPDDR4_DQ2_B: U3.U30(HPIO11_9A/DP2_DQ18) U5.V2(DQ2_B)
LPDDR4_DQ2_C: U3.W26(HPIO11_8A/DP2_DQ34) U119.E2(DQ2_A)
LPDDR4_DQ2_D: U3.AJ32(HPIO9_1B/DP2_DQ50) U119.V2(DQ2_B)
LPDDR4_DQ3_A: U3.AE24(HPIO10_14A/DP2_DQ03) U5.F2(DQ3_A)
LPDDR4_DQ3_B: U3.U31(HPIO11_9B/DP2_DQ19) U5.U2(DQ3_B)
LPDDR4_DQ3_C: U3.V26(HPIO11_8B/DP2_DQ35) U119.F2(DQ3_A)
LPDDR4_DQ3_D: U3.AJ31(HPIO9_1A/DP2_DQ51) U119.U2(DQ3_B)
LPDDR4_DQ4_A: U3.AA21(HPIO10_22B/DP2_DQ04) U5.F4(DQ4_A)
LPDDR4_DQ4_B: U3.Y28(HPIO11_1A/DP2_DQ20) U5.U4(DQ4_B)
LPDDR4_DQ4_C: U3.AA27(HPIO11_0A/DP2_DQ36) U119.F4(DQ4_A)
LPDDR4_DQ4_D: U3.AK34(HPIO9_9B/DP2_DQ52) U119.U4(DQ4_B)
LPDDR4_DQ5_A: U3.Y21(HPIO10_22A/DP2_DQ05) U5.E4(DQ5_A)
LPDDR4_DQ5_B: U3.AA28(HPIO11_1B/DP2_DQ21) U5.V4(DQ5_B)
LPDDR4_DQ5_C: U3.Y27(HPIO11_0B/DP2_DQ37) U119.E4(DQ5_A)
LPDDR4_DQ5_D: U3.AK33(HPIO9_9A/DP2_DQ53) U119.V4(DQ5_B)
LPDDR4_DQ6_A: U3.AB24(HPIO10_16B/DP2_DQ06) U5.C4(DQ6_A)
LPDDR4_DQ6_B: U3.V30(HPIO11_7A/DP2_DQ22) U5.Y4(DQ6_B)
LPDDR4_DQ6_C: U3.AA26(HPIO11_6A/DP2_DQ38) U119.C4(DQ6_A)
LPDDR4_DQ6_D: U3.AJ33(HPIO9_3B/DP2_DQ54) U119.Y4(DQ6_B)
LPDDR4_DQ7_A: U3.AC24(HPIO10_16A/DP2_DQ07) U5.B4(DQ7_A)
LPDDR4_DQ7_B: U3.W30(HPIO11_7B/DP2_DQ23) U5.AA4(DQ7_B)
LPDDR4_DQ7_C: U3.Y26(HPIO11_6B/DP2_DQ39) U119.B4(DQ7_A)
LPDDR4_DQ7_D: U3.AJ34(HPIO9_3A/DP2_DQ55) U119.AA4(DQ7_B)
LPDDR4_DQ8_A: U3.AD34(HPIO10_21B/DP2_DQ08) U5.B11(DQ8_A)
LPDDR4_DQ8_B: U3.AA24(HPIO11_16A/DP2_DQ24) U5.AA11(DQ8_B)
LPDDR4_DQ8_C: U3.AF32(HPIO9_6B/DP2_DQ40) U119.B11(DQ8_A)
LPDDR4_DQ8_D: U3.AJ29(HPIO9_20B/DP2_DQ56) U119.AA11(DQ8_B)
LPDDR4_DQ9_A: U3.AD33(HPIO10_21A/DP2_DQ09) U5.C11(DQ9_A)
LPDDR4_DQ9_B: U3.Y24(HPIO11_16B/DP2_DQ25) U5.Y11(DQ9_B)
LPDDR4_DQ9_C: U3.AG32(HPIO9_6A/DP2_DQ41) U119.C11(DQ9_A)
LPDDR4_DQ9_D: U3.AJ28(HPIO9_20A/DP2_DQ57) U119.Y11(DQ9_B)
LPDDR4_DQ10_A: U3.AE32(HPIO10_15B/DP2_DQ10) U5.E11(DQ10_A)
LPDDR4_DQ10_B: U3.U23(HPIO11_22A/DP2_DQ26) U5.V11(DQ10_B)
LPDDR4_DQ10_C: U3.AF29(HPIO9_0B/DP2_DQ42) U119.E11(DQ10_A)
LPDDR4_DQ10_D: U3.AG28(HPIO9_14B/DP2_DQ58) U119.V11(DQ10_B)
LPDDR4_DQ11_A: U3.AE31(HPIO10_15A/DP2_DQ11) U5.F11(DQ11_A)
LPDDR4_DQ11_B: U3.U22(HPIO11_22B/DP2_DQ27) U5.U11(DQ11_B)
LPDDR4_DQ11_C: U3.AF28(HPIO9_0A/DP2_DQ43) U119.F11(DQ11_A)
LPDDR4_DQ11_D: U3.AG27(HPIO9_14A/DP2_DQ59) U119.U11(DQ11_B)
LPDDR4_DQ12_A: U3.AE33(HPIO10_23B/DP2_DQ12) U5.F9(DQ12_A)
LPDDR4_DQ12_B: U3.U25(HPIO11_14A/DP2_DQ28) U5.U9(DQ12_B)
LPDDR4_DQ12_C: U3.AG34(HPIO9_8B/DP2_DQ44) U119.F9(DQ12_A)
LPDDR4_DQ12_D: U3.AG26(HPIO9_22B/DP2_DQ60) U119.U9(DQ12_B)
LPDDR4_DQ13_A: U3.AE34(HPIO10_23A/DP2_DQ13) U5.E9(DQ13_A)
LPDDR4_DQ13_B: U3.T25(HPIO11_14B/DP2_DQ29) U5.V9(DQ13_B)
LPDDR4_DQ13_C: U3.AH34(HPIO9_8A/DP2_DQ45) U119.E9(DQ13_A)
LPDDR4_DQ13_D: U3.AH26(HPIO9_22A/DP2_DQ61) U119.V9(DQ13_B)
LPDDR4_DQ14_A: U3.AB34(HPIO10_17B/DP2_DQ14) U5.C9(DQ14_A)
LPDDR4_DQ14_B: U3.U24(HPIO11_20A/DP2_DQ30) U5.Y9(DQ14_B)
LPDDR4_DQ14_C: U3.AG30(HPIO9_2B/DP2_DQ46) U119.C9(DQ14_A)
LPDDR4_DQ14_D: U3.AG29(HPIO9_16B/DP2_DQ62) U119.Y9(DQ14_B)
LPDDR4_DQ15_A: U3.AB33(HPIO10_17A/DP2_DQ15) U5.B9(DQ15_A)
LPDDR4_DQ15_B: U3.T24(HPIO11_20B/DP2_DQ31) U5.AA9(DQ15_B)
LPDDR4_DQ15_C: U3.AF30(HPIO9_2A/DP2_DQ47) U119.B9(DQ15_A)
LPDDR4_DQ15_D: U3.AH29(HPIO9_16A/DP2_DQ63) U119.AA9(DQ15_B)
LPDDR4_LDM_A: U3.AC21(HPIO10_24A/PCLKRT10_2/DP2_DM0) U5.C3(DMI0_A)
LPDDR4_LDM_B: U3.V32(HPIO11_11A/PCLKT11_1/PCLKRT11_1/DP2_DM2) U5.Y3(DMI0_B)
LPDDR4_LDM_C: U3.V25(HPIO11_10A/PCLKT11_0/PCLKRT11_0/DP2_DM4) U119.C3(DMI0_A)
LPDDR4_LDM_D: U3.AM30(HPIO9_11A/PCLKT9_1/PCLKRT9_1/DP2_DM6) U119.Y3(DMI0_B)
LPDDR4_LDQS_A_N: U3.AD23(HPIO10_18B/DP2_DQSN0) U5.E3(DQS0_C_A)
LPDDR4_LDQS_A_P: U3.AC23(HPIO10_18A/DP2_DQS0) U5.D3(DQS0_T_A)
LPDDR4_LDQS_B_N: U3.W29(HPIO11_5B/DP2_DQSN2) U5.V3(DQS0_C_B)
LPDDR4_LDQS_B_P: U3.Y29(HPIO11_5A/DP2_DQS2) U5.W3(DQS0_T_B)
LPDDR4_LDQS_C_N: U3.V27(HPIO11_4B/DP2_DQSN4) U119.E3(DQS0_C_A)
LPDDR4_LDQS_C_P: U3.U27(HPIO11_4A/DP2_DQS4) U119.D3(DQS0_T_A)
LPDDR4_LDQS_D_N: U3.AK30(HPIO9_5B/DP2_DQSN6) U119.V3(DQS0_C_B)
LPDDR4_LDQS_D_P: U3.AK29(HPIO9_5A/DP2_DQS6) U119.W3(DQS0_T_B)
LPDDR4_RESET: R596.1 U3.AF34(HPIO10_25B/PCLKRC10_3/DP2_RST_N) U5.T11(RESET_N) U119.T11(RESET_N)
LPDDR4_UDM_A: U3.AF33(HPIO10_25A/PCLKRT10_3/DP2_DM1) U5.C10(DMI1_A)
LPDDR4_UDM_B: U3.V22(HPIO11_24A/PCLKRT11_2/DP2_DM3) U5.Y10(DMI1_B)
LPDDR4_UDM_C: U3.AG33(HPIO9_10A/PCLKT9_0/PCLKRT9_0/DP2_DM5) U119.C10(DMI1_A)
LPDDR4_UDM_D: U3.AJ27(HPIO9_24A/PCLKRT9_2/DP2_DM7) U119.Y10(DMI1_B)
LPDDR4_UDQS_A_N: U3.AC33(HPIO10_19B/DP2_DQSN1) U5.E10(DQS1_C_A)
LPDDR4_UDQS_A_P: U3.AC34(HPIO10_19A/DP2_DQS1) U5.D10(DQS1_T_A)
LPDDR4_UDQS_B_N: U3.W24(HPIO11_18B/DP2_DQSN3) U5.V10(DQS1_C_B)
LPDDR4_UDQS_B_P: U3.W23(HPIO11_18A/DP2_DQS3) U5.W10(DQS1_T_B)
LPDDR4_UDQS_C_N: U3.AG31(HPIO9_4B/DP2_DQSN5) U119.E10(DQS1_C_A)
LPDDR4_UDQS_C_P: U3.AF31(HPIO9_4A/DP2_DQS5) U119.D10(DQS1_T_A)
LPDDR4_UDQS_D_N: U3.AJ30(HPIO9_18B/DP2_DQSN7) U119.V10(DQS1_C_B)
LPDDR4_UDQS_D_P: U3.AH30(HPIO9_18A/DP2_DQS7) U119.W10(DQS1_T_B)
ODT_CA_A: JP83.2 U5.G2(ODT_CA_A)
ODT_CA_B: JP84.2 U5.T2(ODT_CA_B)
ODT_CA_C: JP85.2 U119.G2(ODT_CA_A)
ODT_CA_D: JP86.2 U119.T2(ODT_CA_B)
PMOD2_1: J6.1 U3.P18(WRIO12_7B/PLLTFB12_IN)
PMOD2_2: J6.2 U3.N19(WRIO12_1A)
PMOD2_3: J6.3 U3.N20(WRIO12_5B)
PMOD2_4: J6.4 U3.P20(WRIO12_5A)
PMOD2_5: J6.7 U3.R17(WRIO12_6B)
PMOD2_6: J6.8 U3.M19(WRIO12_3A)
PMOD2_7: J6.9 U3.M20(WRIO12_3B/PCLKT12_0/PCLKRT12_0)
PMOD2_8: J6.10 U3.P19(WRIO12_7A/PLLT12_IN)
PMOD3_1: J7.1 U3.P14(WRIO12_4B)
PMOD3_2: J7.2 U3.N15(WRIO12_0A)
PMOD3_3: J7.3 U3.N16(WRIO12_2B)
PMOD3_4: J7.4 U3.R16(WRIO12_6A)
PMOD3_5: J7.7 U3.P13(WRIO12_4A)
PMOD3_6: J7.8 U3.N14(WRIO12_0B)
PMOD3_7: J7.9 U3.P15(WRIO12_2A)
PMOD3_8: J7.10 U3.N17(WRIO12_1B/PCLK12_1/PCLKRT12_1)
RASP_5V: C599.1 JP13.2 JP26.2 JP26.4
RASP_ID_SC: JP26.28 R103.1 U3.R12(WRIO14_7A)
RASP_ID_SD: JP26.27 R104.1 U3.T11(WRIO14_7B)
RASP_IO02: JP26.3 U3.V15(WRIO13_6B)
RASP_IO03: JP26.5 U3.T13(WRIO13_7A)
RASP_IO04: JP26.7 ; also on sheet 5
RASP_IO05: JP26.29 R108.2 U3.V8(WRIO14_6A)
RASP_IO06: JP26.31 R105.2 U3.W8(WRIO14_6B)
RASP_IO07: JP26.26 ; also on sheet 5
RASP_IO08: JP26.24 ; also on sheet 5
RASP_IO09: JP26.21 ; also on sheet 5
RASP_IO10: JP26.19 ; also on sheet 5
RASP_IO11: JP26.23 R106.2 U3.U12(WRIO14_5A/PCLKRT14_0)
RASP_IO12: JP26.32 ; also on sheet 5
RASP_IO13: JP26.33 U3.R9(WRIO14_8B)
RASP_IO14: JP26.8 U3.V14(WRIO13_5B)
RASP_IO15: JP26.10 U3.R13(WRIO13_7B)
RASP_IO16: JP26.36 ; also on sheet 5
RASP_IO17: JP26.11 U3.V16(WRIO13_6A)
RASP_IO18: JP26.12 R107.2 U3.T12(WRIO14_5B)
RASP_IO19: JP26.35 U3.R11(WRIO14_9A)
RASP_IO20: JP26.38 ; also on sheet 4
RASP_IO21: JP26.40 ; also on sheet 4
RASP_IO22: JP26.15 ; also on sheet 4
RASP_IO23: JP26.16 ; also on sheet 5
RASP_IO24: JP26.18 ; also on sheet 5
RASP_IO25: JP26.22 ; also on sheet 4
RASP_IO26: JP26.37 U3.T9(WRIO14_8A)
RASP_IO27: JP26.13 ; also on sheet 5
SCL: R103.2 ; also on sheet 3
SDA: R104.2 ; also on sheet 3
SEG_A: R332.2 U3.V10(WRIO14_0A)
SEG_B: R333.2 U3.T10(WRIO14_0B)
SEG_C: R334.2 U3.V12(WRIO14_1A)
SEG_D: R335.2 U3.V13(WRIO14_1B)
SEG_DP: R331.2 U3.W11(WRIO14_3B)
SEG_E: R336.2 U3.W10(WRIO14_2A)
SEG_F: R337.2 U3.V11(WRIO14_2B)
SEG_G: R338.2 U3.W12(WRIO14_3A)
TCK: R106.1 ; also on sheet 3 5
TDI: R105.1 ; also on sheet 3 5
TDO: R108.1 ; also on sheet 3 5
TMS: R107.1 ; also on sheet 3 5
VFMC1_ADJ: JP70.1 JP72.1 JP74.1 ; also on sheet 7 8
VFMC2_ADJ: JP76.1 JP78.1 ; also on sheet 8 10
N19901221: C36.1 J6.6 J6.12 J23.2 R82.2
N20899580: R294.1 U3.U26(EXT_RES11/DP2_EXT_RES11)
N20899618: R290.1 U3.AE27(EXT_RES10/DP2_EXT_RES10)
N20900730: R291.2 U5.A5(ZQ0)
N20922301: C525.1 J7.6 J7.12 J57.2 R298.2
N21005513: D60.3(DP) R331.1
N21005532: D60.11(A) R332.1
N21005551: D60.7(B) R333.1
N21005570: D60.4(C) R334.1
N21005589: D60.2(D) R335.1
N21005608: D60.1(E) R336.1
N21005627: D60.10(F) R337.1
N21005646: D60.5(G) R338.1
N21008142: Q2.B R339.2 R340.1
N21008495: Q3.B R341.2 R342.1
N21008871: Q4.B R343.2 R344.1
N21071175: R345.2 U3.U15(WRIO13_3B/PCLKRT13_0)
N21123855: C600.1 JP12.2 JP26.1 JP26.17
N21269868: R538.2 Y1.5(OUT#)
N21271826: D61.A R169.1
N21271847: Q7.B R229.1
N21271871: D61.K Q7.C
N21271879: C385.1 U17.6(BST)
N21271891: C385.2 L8.1 U17.2(SW)
N21271907: R231.2 R232.1 U17.4(FB)
N21272003: R233.2 R234.1 U17.5(EN)
N21279835: D63.A R417.1
N21279856: Q8.B R416.1
N21279868: D63.K Q8.C
N21279888: C638.1 U35.6(BST)
N21279900: C638.2 L15.1 U35.2(SW)
N21279916: R420.2 R421.1 U35.4(FB)
N21279996: R418.2 R419.1 U35.5(EN)
N21283467: C734.1 R572.2 R716.1 U36.5(EN)
N21283516: R288.1 R424.1 R425.2 U36.4(FB)
N21283565: D64.A R427.1
N21283586: Q9.B R426.1
N21283590: D64.K Q9.C
N21283614: C645.1 U36.6(BST)
N21283618: C645.2 L5.1 U36.2(SW)
N21285415: R428.2 R429.1 U37.5(EN)
N21285466: R430.1 R431.2 U37.4(FB)
N21285515: D65.A R433.1
N21285536: Q10.B R432.1
N21285540: D65.K Q10.C
N21285564: C649.1 U37.6(BST)
N21285568: C649.2 L16.1 U37.2(SW)
N21287544: R434.2 R435.1 U38.5(EN)
N21287595: R436.1 R437.2 U38.4(FB)
N21287644: D66.A R439.1
N21287665: Q11.B R438.1
N21287669: D66.K Q11.C
N21287693: C653.1 U38.6(BST)
N21287697: C653.2 L17.1 U38.2(SW)
N21298381: D68.A R447.1
N21298402: Q13.B R446.1
N21298414: D68.K Q13.C
N21298430: C658.1 U40.6(BST)
N21298442: C658.2 L19.1 U40.2(SW)
N21298458: R450.2 R451.1 U40.4(FB)
N21298538: R448.2 R449.1 U40.5(EN)
N21310610: D69.A R453.1
N21310631: Q14.B R452.1
N21310643: D69.K Q14.C
N21310659: C662.1 U41.6(BST)
N21310671: C662.2 L20.1 U41.2(SW)
N21310687: R456.2 R457.1 U41.4(FB)
N21310767: R454.2 R455.1 U41.5(EN)
N21316067: R440.1 R441.2 U39.5(EN)
N21316093: R442.1 R445.2 U39.4(FB)
N21316143: D67.A R444.1
N21316167: Q12.B R443.1
N21316171: D67.K Q12.C
N21316188: C657.1 U39.6(BST)
N21316200: C657.2 L18.1 U39.2(SW)
N21377300: R490.2 R491.1 R492.1 R493.2 R548.2
N21466678: R537.2 Y1.4(OUT)
N22007255: C94.1 R287.1 R288.2
N22604437: R185.2 U116.3(CE)
N22604439: R189.1 R192.2 U116.1(Vfb)
N22625096: R633.2 U119.A5(ZQ0)
N22703478: JP83.3 R292.1
N22703481: JP83.1 R598.2
N22703488: JP84.3 R597.2
N22703491: JP84.1 R293.1
N22703555: JP85.3 R646.1
N22703558: JP85.1 R645.2
N22703565: JP86.3 R644.2
N22703568: JP86.1 R647.1
N23050396: R685.1 U3.AF26(EXT_RES9/DP2_EXT_RES9)

Not connected (* = marked no-connect by the designer): D60 6(NC)*; U3 AA29(HPIO11_25B/PCLKRC11_3/DP2_RAS_N)* AA30(HPIO11_25A/PCLKRT11_3/DP2_BA0)* AA32(HPIO10_9A/DP2_MA10)* AA33(HPIO10_11B/PCLKC10_1/PCLKRC10_1/DP2_MA13)* AA34(HPIO10_11A/PCLKT10_1/PCLKRT10_1/DP2_MA12)* AB21(HPIO10_24B/PCLKRC10_2/DP2_ALERT_N)* AB30(HPIO10_1A/DP2_MCLKT1)* AB31(HPIO10_7B/DP2_MA9)* AB32(HPIO10_9B/DP2_MA11)* AC27(HPIO10_8B/DP2_MA6)* AC30(HPIO10_1B/DP2_MCLKC1)* AD26(HPIO10_10A/PCLKT10_0/PCLKRT10_0/DP2_MA7)* AD29(HPIO10_3B/DP2_ODT1)* AD30(HPIO10_3A/DP2_CKE1)* AE26(HPIO10_10B/PCLKC10_0/PCLKRC10_0/DP2_MA8)* AE28(HPIO10_12A/VREF10/DP2_VREF10)* AE29(HPIO10_5A/DP2_ODT0)* AE30(HPIO10_5B/DP2_CS_N1)* AF27(HPIO9_12A/VREF9/DP2_VREF9)* AH33(HPIO9_10B/PCLKC9_0/PCLKRC9_0)* AJ26(HPIO9_24B/PCLKRC9_2)* AL30(HPIO9_11B/PCLKC9_1/PCLKRC9_1)* AL33(HPIO9_15A/DP2_DQ67)* AL34(HPIO9_15B/DP2_DQ66)* AM31(HPIO9_13B/PLLC9_IN)* AM32(HPIO9_13A/PLLT9_IN)* AM33(HPIO9_17A/DP2_DQ71)* AM34(HPIO9_17B/DP2_DQ70) AN30(HPIO9_25B/PCLKRC9_3)* AN31(HPIO9_23B/DP2_DQ68)* AN32(HPIO9_21A/DP2_DQ65)* AN33(HPIO9_19B/DP2_DQSN8)* AN34(HPIO9_19A/DP2_DQS8)* AP30(HPIO9_25A/PCLKRT9_3/DP2_DM8)* AP31(HPIO9_23A/DP2_DQ69)* AP32(HPIO9_21B/DP2_DQ64)* T26(HPIO11_12A/VREF11/DP2_VREF11)* U32(HPIO11_13B/PLLC11_IN)* U33(HPIO11_13A/PLLT11_IN)* U34(HPIO11_17A/DP2_MCLKT2)* V31(HPIO11_11B/PCLKC11_1/PCLKRC11_1)* V33(HPIO11_15A/DP2_MCLKT3)* V34(HPIO11_17B/DP2_MCLKC2)* W22(HPIO11_24B/PCLKRC11_2/DP2_CAS_N)* W25(HPIO11_10B/PCLKC11_0/PCLKRC11_0)* W33(HPIO11_15B/DP2_MCLKC3)* W34(HPIO11_19B/DP2_MA15)* Y30(HPIO11_23B/DP2_BA1)* Y31(HPIO11_23A/DP2_BA2)* Y32(HPIO11_21A/DP2_MA14)* Y33(HPIO11_21B/DP2_WE_N)* Y34(HPIO11_19A/DP2_MA16)*; U5 A1(DNU)* A2(DNU)* A8(NC)* A11(DNU)* A12(DNU)* AA1(DNU)* AA12(DNU)* AB1(DNU)* AB2(DNU)* AB11(DNU)* AB12(DNU)* B1(DNU)* B12(DNU)* G11(NC)* H3(NC)* J5(NC)* K5(NC)* K8(NC)* N5(NC)* N8(NC)* P5(NC)* R3(NC)*; U119 A1(DNU)* A2(DNU)* A8(NC)* A11(DNU)* A12(DNU)* AA1(DNU)* AA12(DNU)* AB1(DNU)* AB2(DNU)* AB11(DNU)* AB12(DNU)* B1(DNU)* B12(DNU)* G11(NC)* H3(NC)* J5(NC)* K5(NC)* K8(NC)* N5(NC)* N8(NC)* P5(NC)* R3(NC)*; Y1 2(NC)*

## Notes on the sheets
sheet 11
- DDR Layout notice: T-branch
  topology for CLK and CA bus
- DDR Layout notice: T-branch
  topology for CLK and CA bus
- Put it at the first fork point
- BANK 11
  1.1V
- BANK 10
  1.1V
- Place R490, R491 &
  R548 close to FPGA
- HCSL
  (Default)
- 100Mhz
- LVDS
- R490
- 49.9 Ohms
- 49.9 Ohms
- R491
- 49.9 Ohms
- 49.9 Ohms
- R492
- DNP
- 2K Ohms
- R493
- DNP
- 2K Ohms
- R537
- 0 Ohm
- 0.1 uF
- R538
- 0 Ohm
- 0.1 uF
- R548
- 0 Ohm
- 0.1 uF
- Place this termination circuit to back side of board
  close to FPGA (not close to Y1)
- BANK 9
  1.1V
sheet 12
- BANK 12
  3.3V
- BANK 13
  3.3V
sheet 13
- 7_SEGMENT_DISPLAY_SECTION
- Raspberry PI and User I/O Connector
- JP12 & JP13 Power For JP26
  Default Open
- PI_3.3V
- PI_5V
- Character Signal Map
- U3 PIN
- D60 PIN
- SEGMENT
- W11
- 3
- DP
- W12
- 5
- G
- V11
- 10
- F
- 1
- E
- W10
- V13
- 2
- D
- 4
- C
- V12
- T10
- 7
- B
- V10
- 11
- A
- BANK 14
  3.3V
sheet 14
- DEFAULT SETTINGS:
  JP58 = OPEN
  JP73 = CLOSED
  JP74 = OPEN
- DEFAULT SETTINGS:
  JP62 = OPEN
  JP77 = CLOSED
  JP78 = OPEN
- DEFAULT SETTINGS:
  JP31 = OPEN
  JP32 = OPEN
  JP33 = OPEN
  JP34 = OPEN
  JP35 = OPEN
  JP36 = CLOSED
- DEFAULT SETTINGS:
  JP60 = OPEN
  JP69 = CLOSED
  JP70 = OPEN
- DEFAULT SETTINGS:
  JP47 = OPEN
  JP48 = OPEN
  JP49 = OPEN
  JP50 = CLOSED
- DEFAULT SETTINGS:
  JP59 = OPEN
  JP71 = CLOSED
  JP72 = OPEN
- DEFAULT SETTINGS:
  JP61 = OPEN
  JP75 = CLOSED
  JP76 = OPEN
- spread across board, easy access,thermal relief
sheet 15
- VCC_CORE = 0.82 V
sheet 16
- Output = 1.35V/2A
- Output = 0.90V/2A
- 5V-1.35V
- 5V-0.9V
- 1.8V/1A
- Voutput = ((R450/R451)+1)*0.8
- Output = 1.00V/2A
- Output = 1.50V/2A
- 5V-1.5V
- 5V-1V
- Output = 1.80V/2A
- Output = 1.10V/2A
- 5V-1.8V
- 5V-1.1V
- Output = 2.50V/2A
- Output = 1.20V/2A
- 5V-2.5V
- 5V-1.2V
